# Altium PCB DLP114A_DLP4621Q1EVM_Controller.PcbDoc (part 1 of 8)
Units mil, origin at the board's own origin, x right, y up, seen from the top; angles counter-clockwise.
Board outline 4803.15 x 2598.43 mil, 14 copper layers (Top Layer, GND 1, SIGNAL 1, GND 2, SIGNAL 2, PWR SPLIT PLANE 1, GND 3, GND 4, PWR SPLIT PLANE 2, SIGNAL 3, GND 5, SIGNAL 4, GND 6, Bottom Layer), stack 91.4 mil thick; 489 components, 394 nets, 1925 pads, 1273 vias.
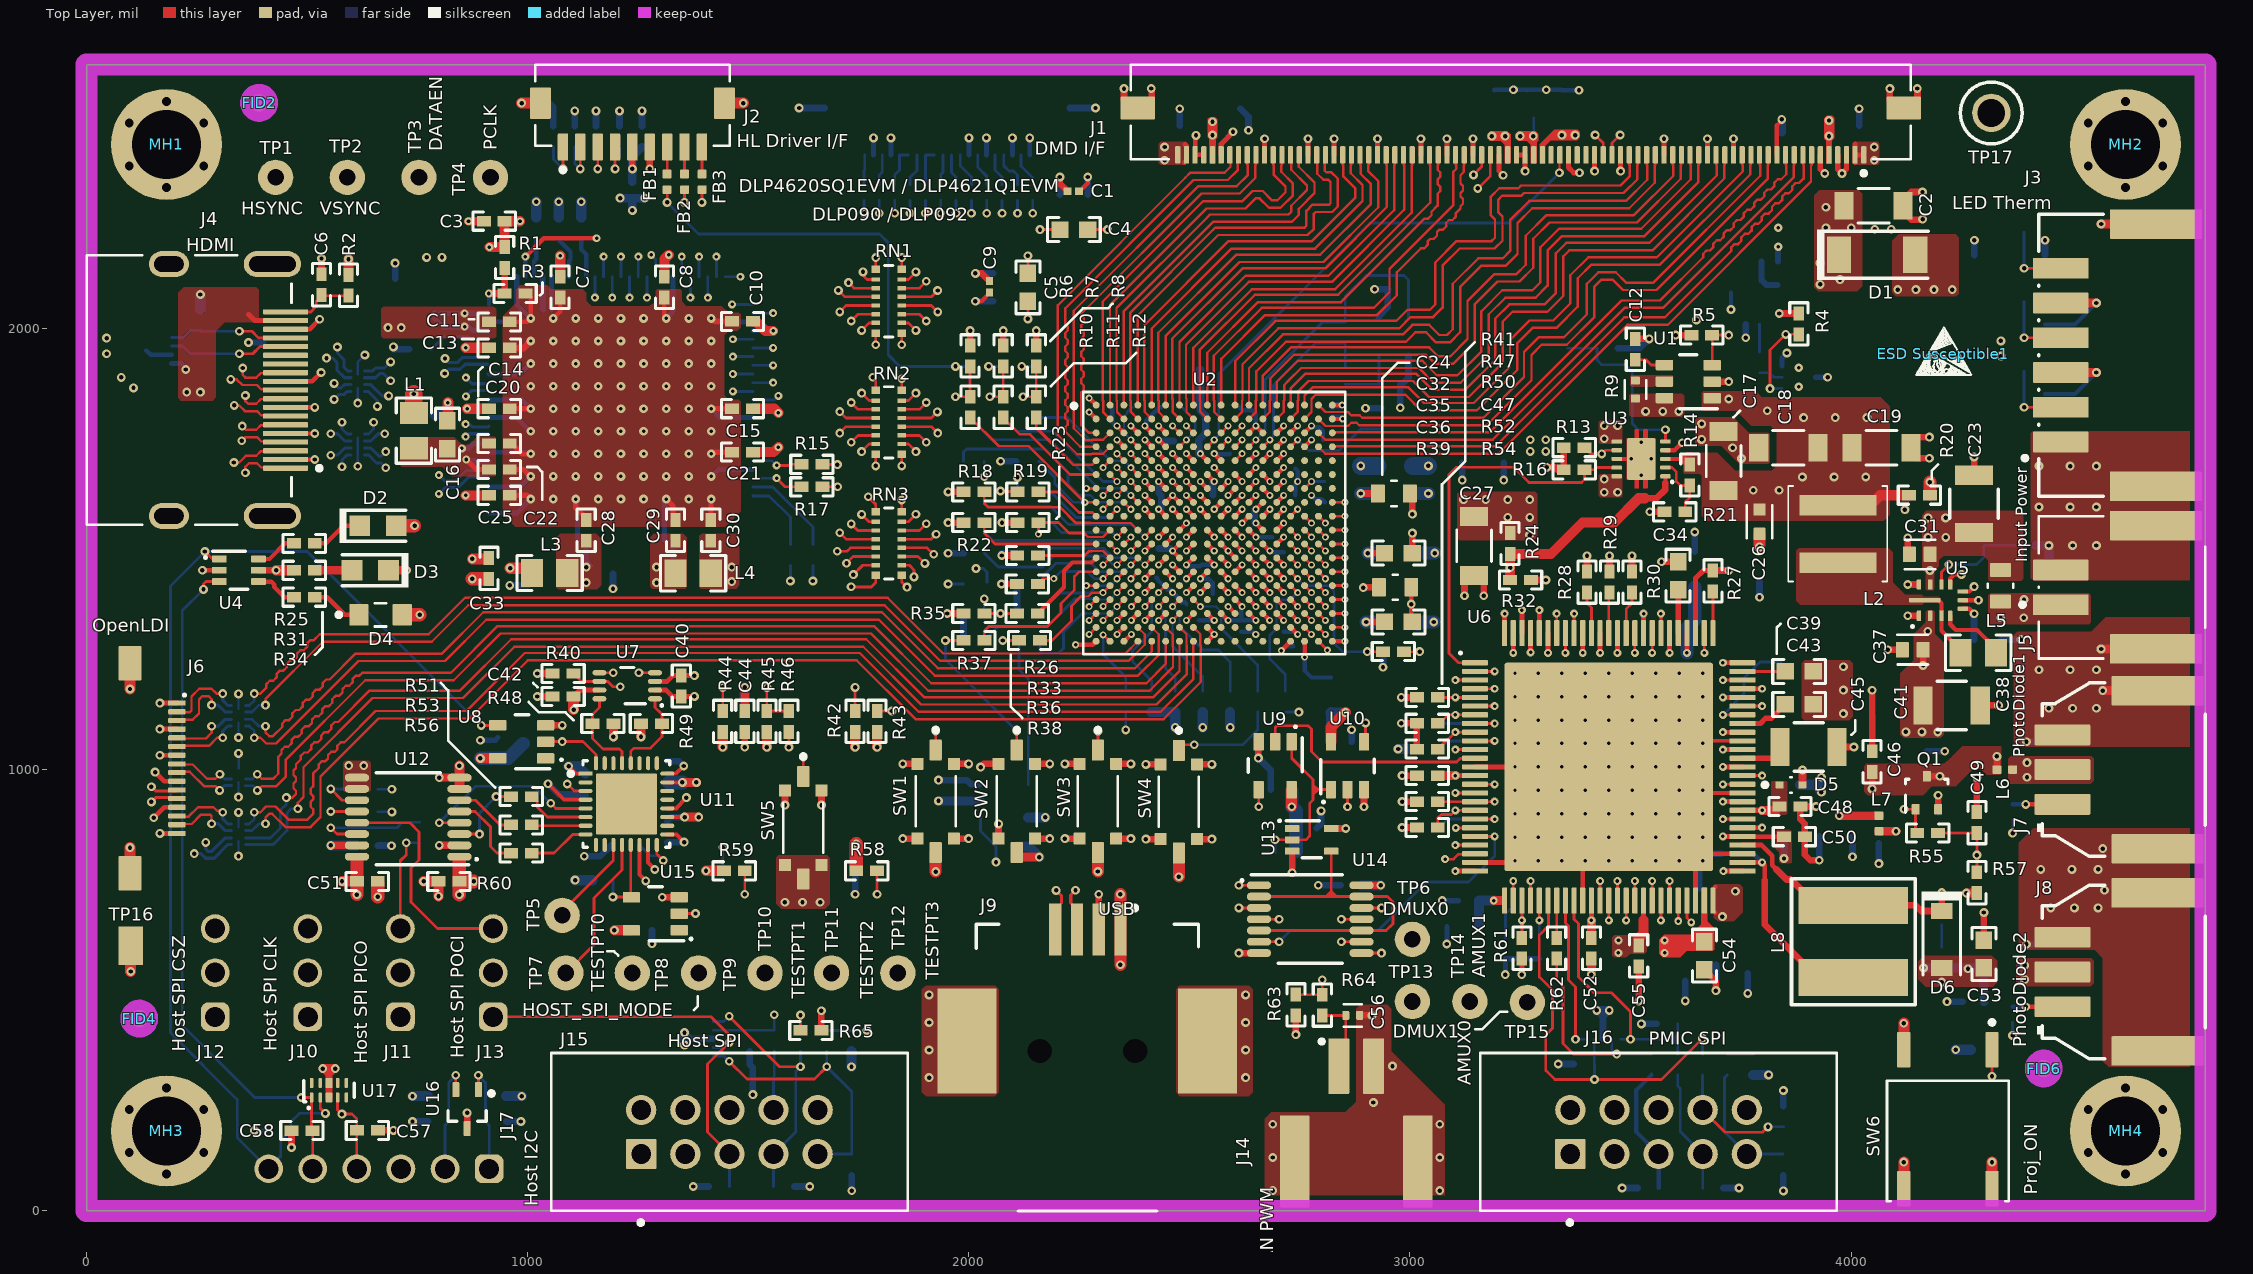
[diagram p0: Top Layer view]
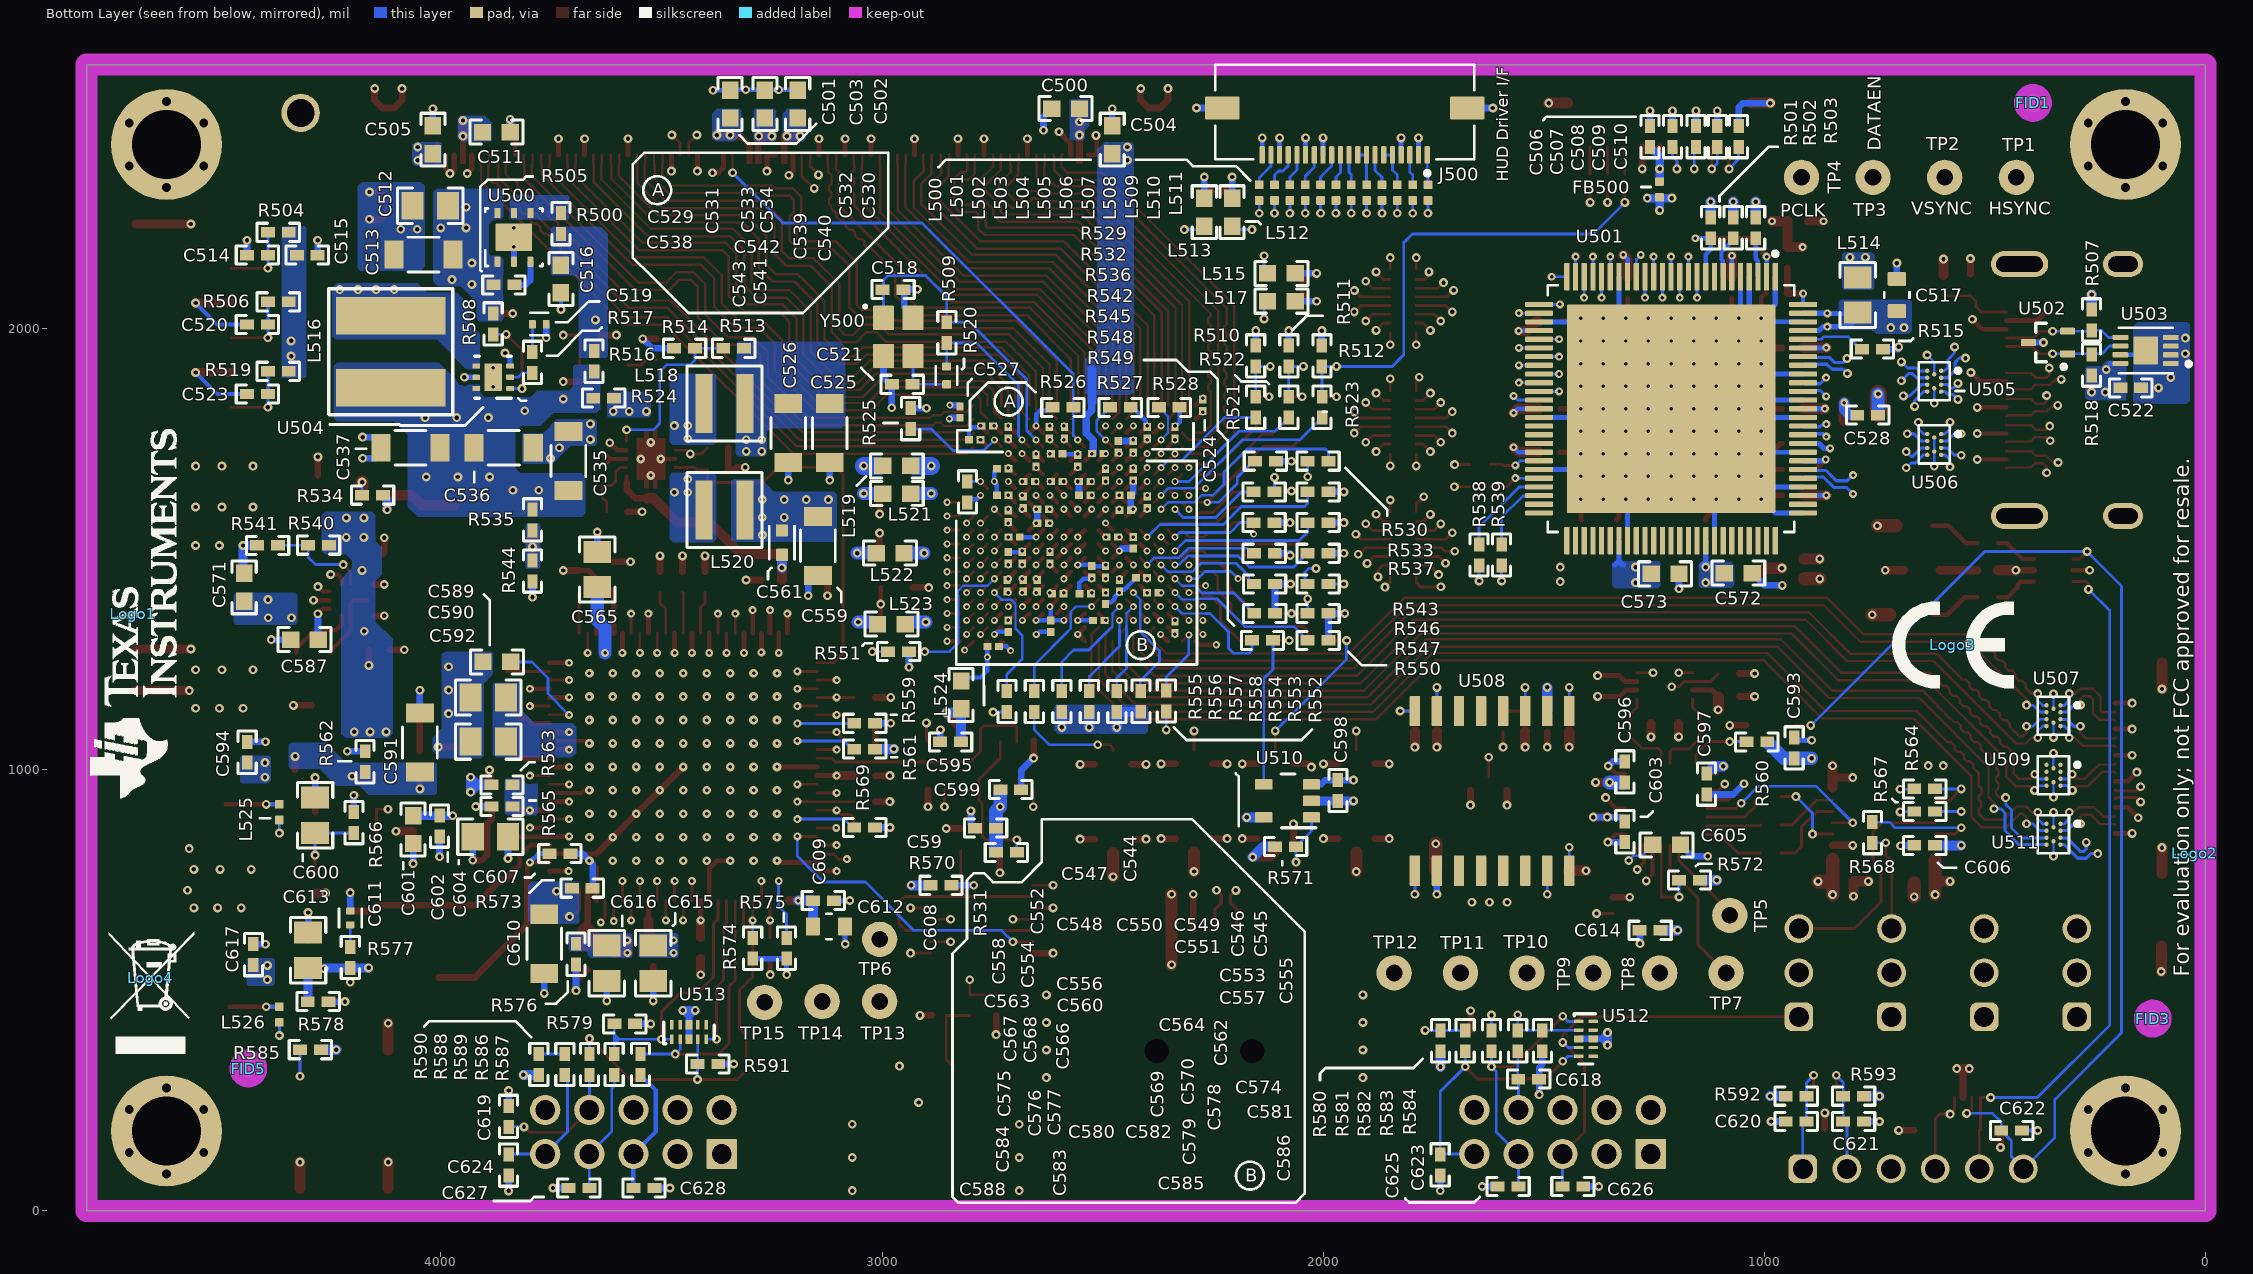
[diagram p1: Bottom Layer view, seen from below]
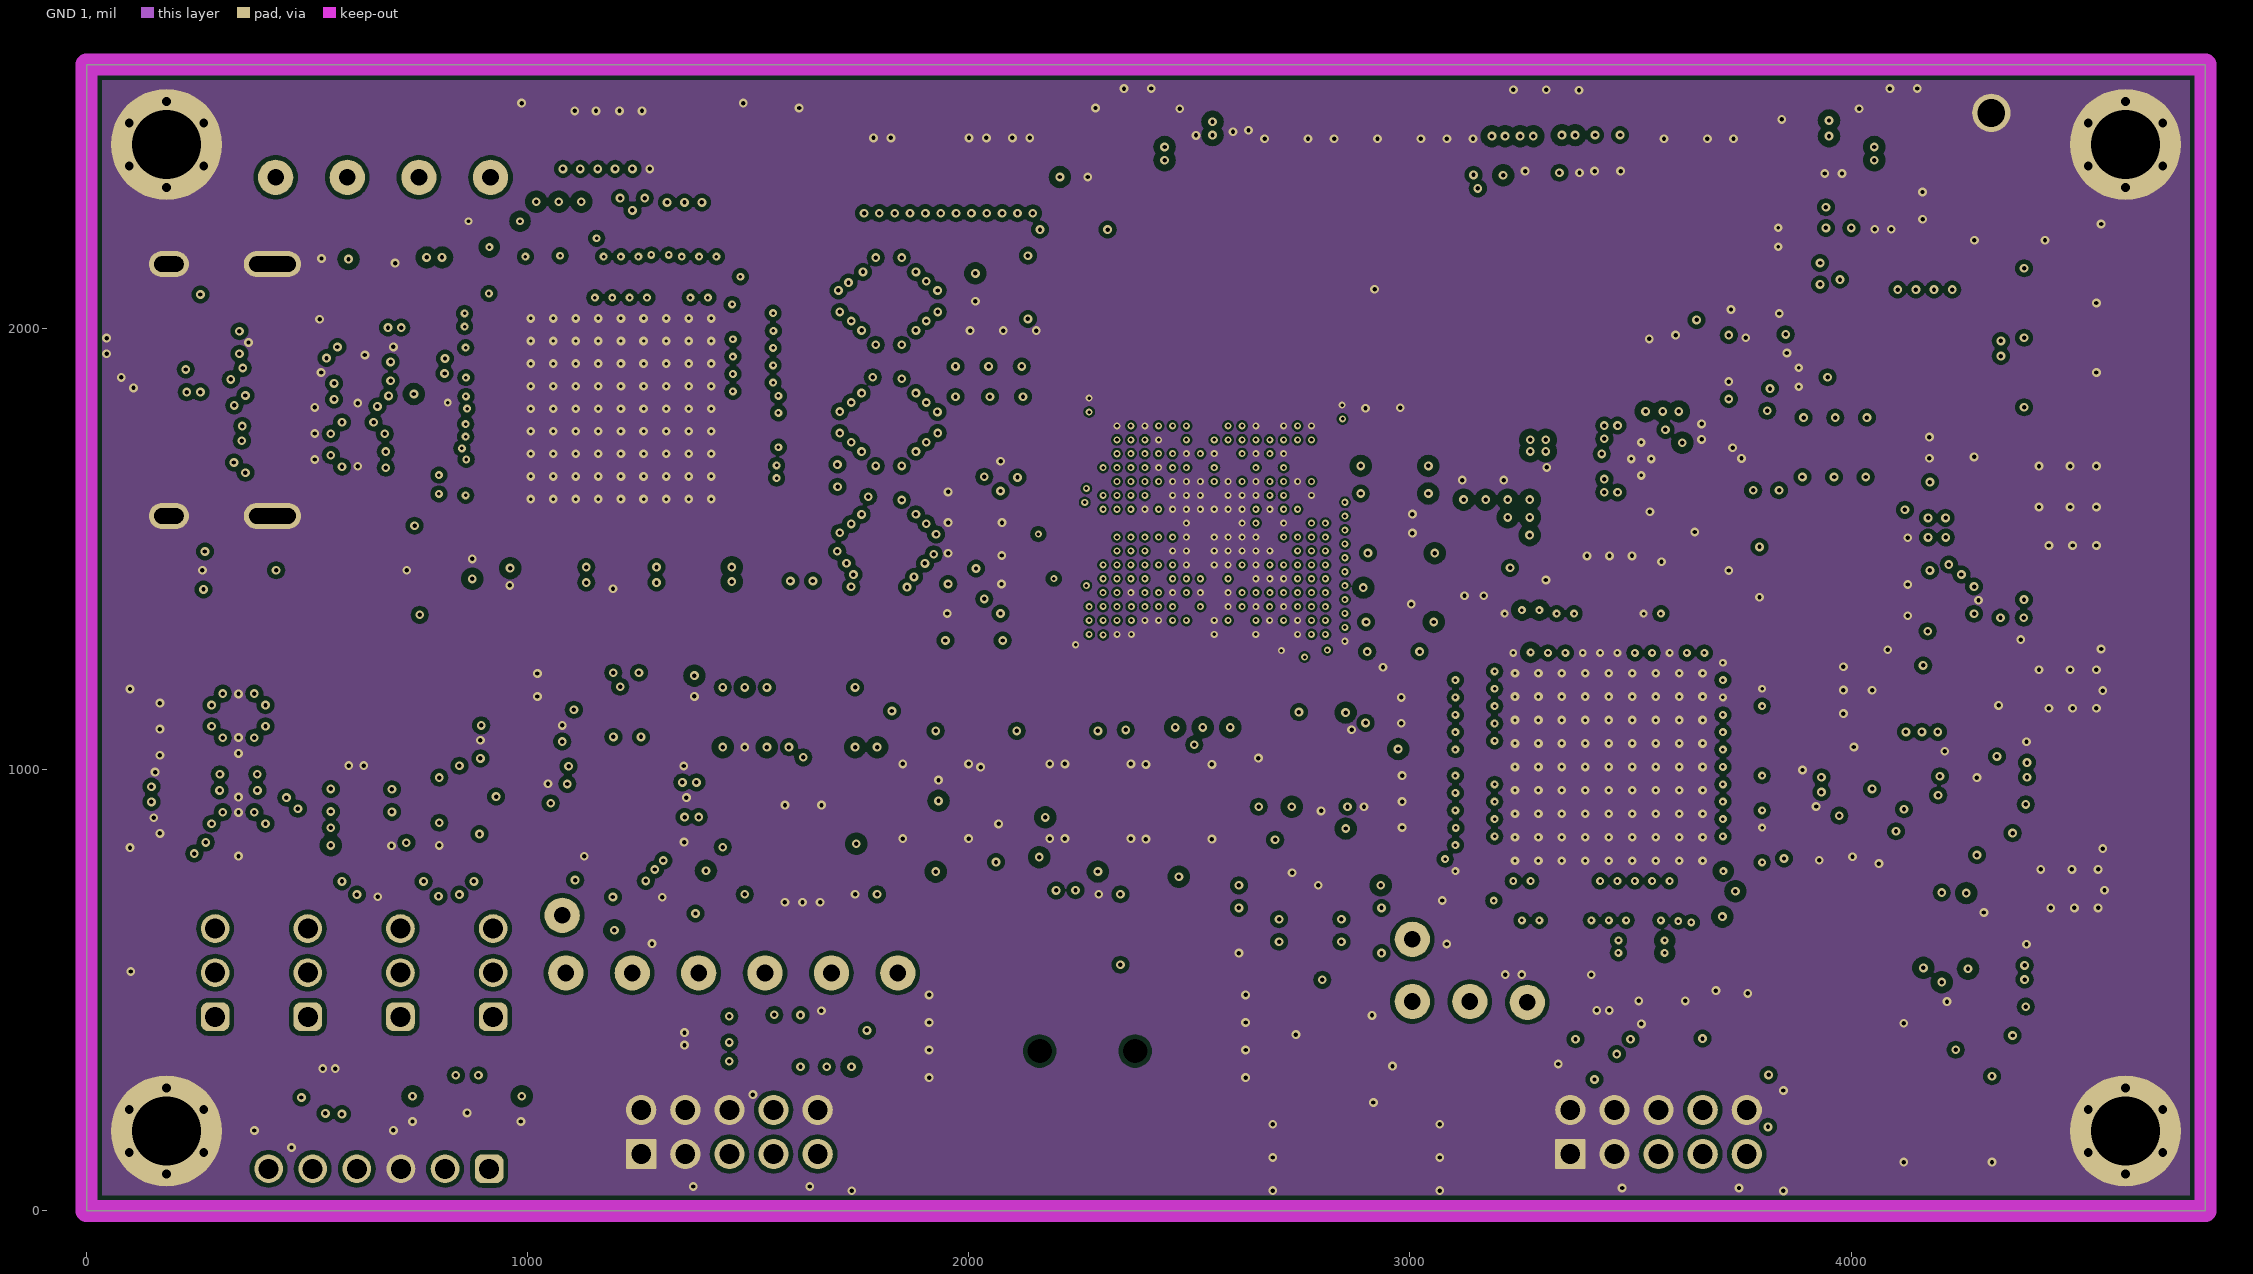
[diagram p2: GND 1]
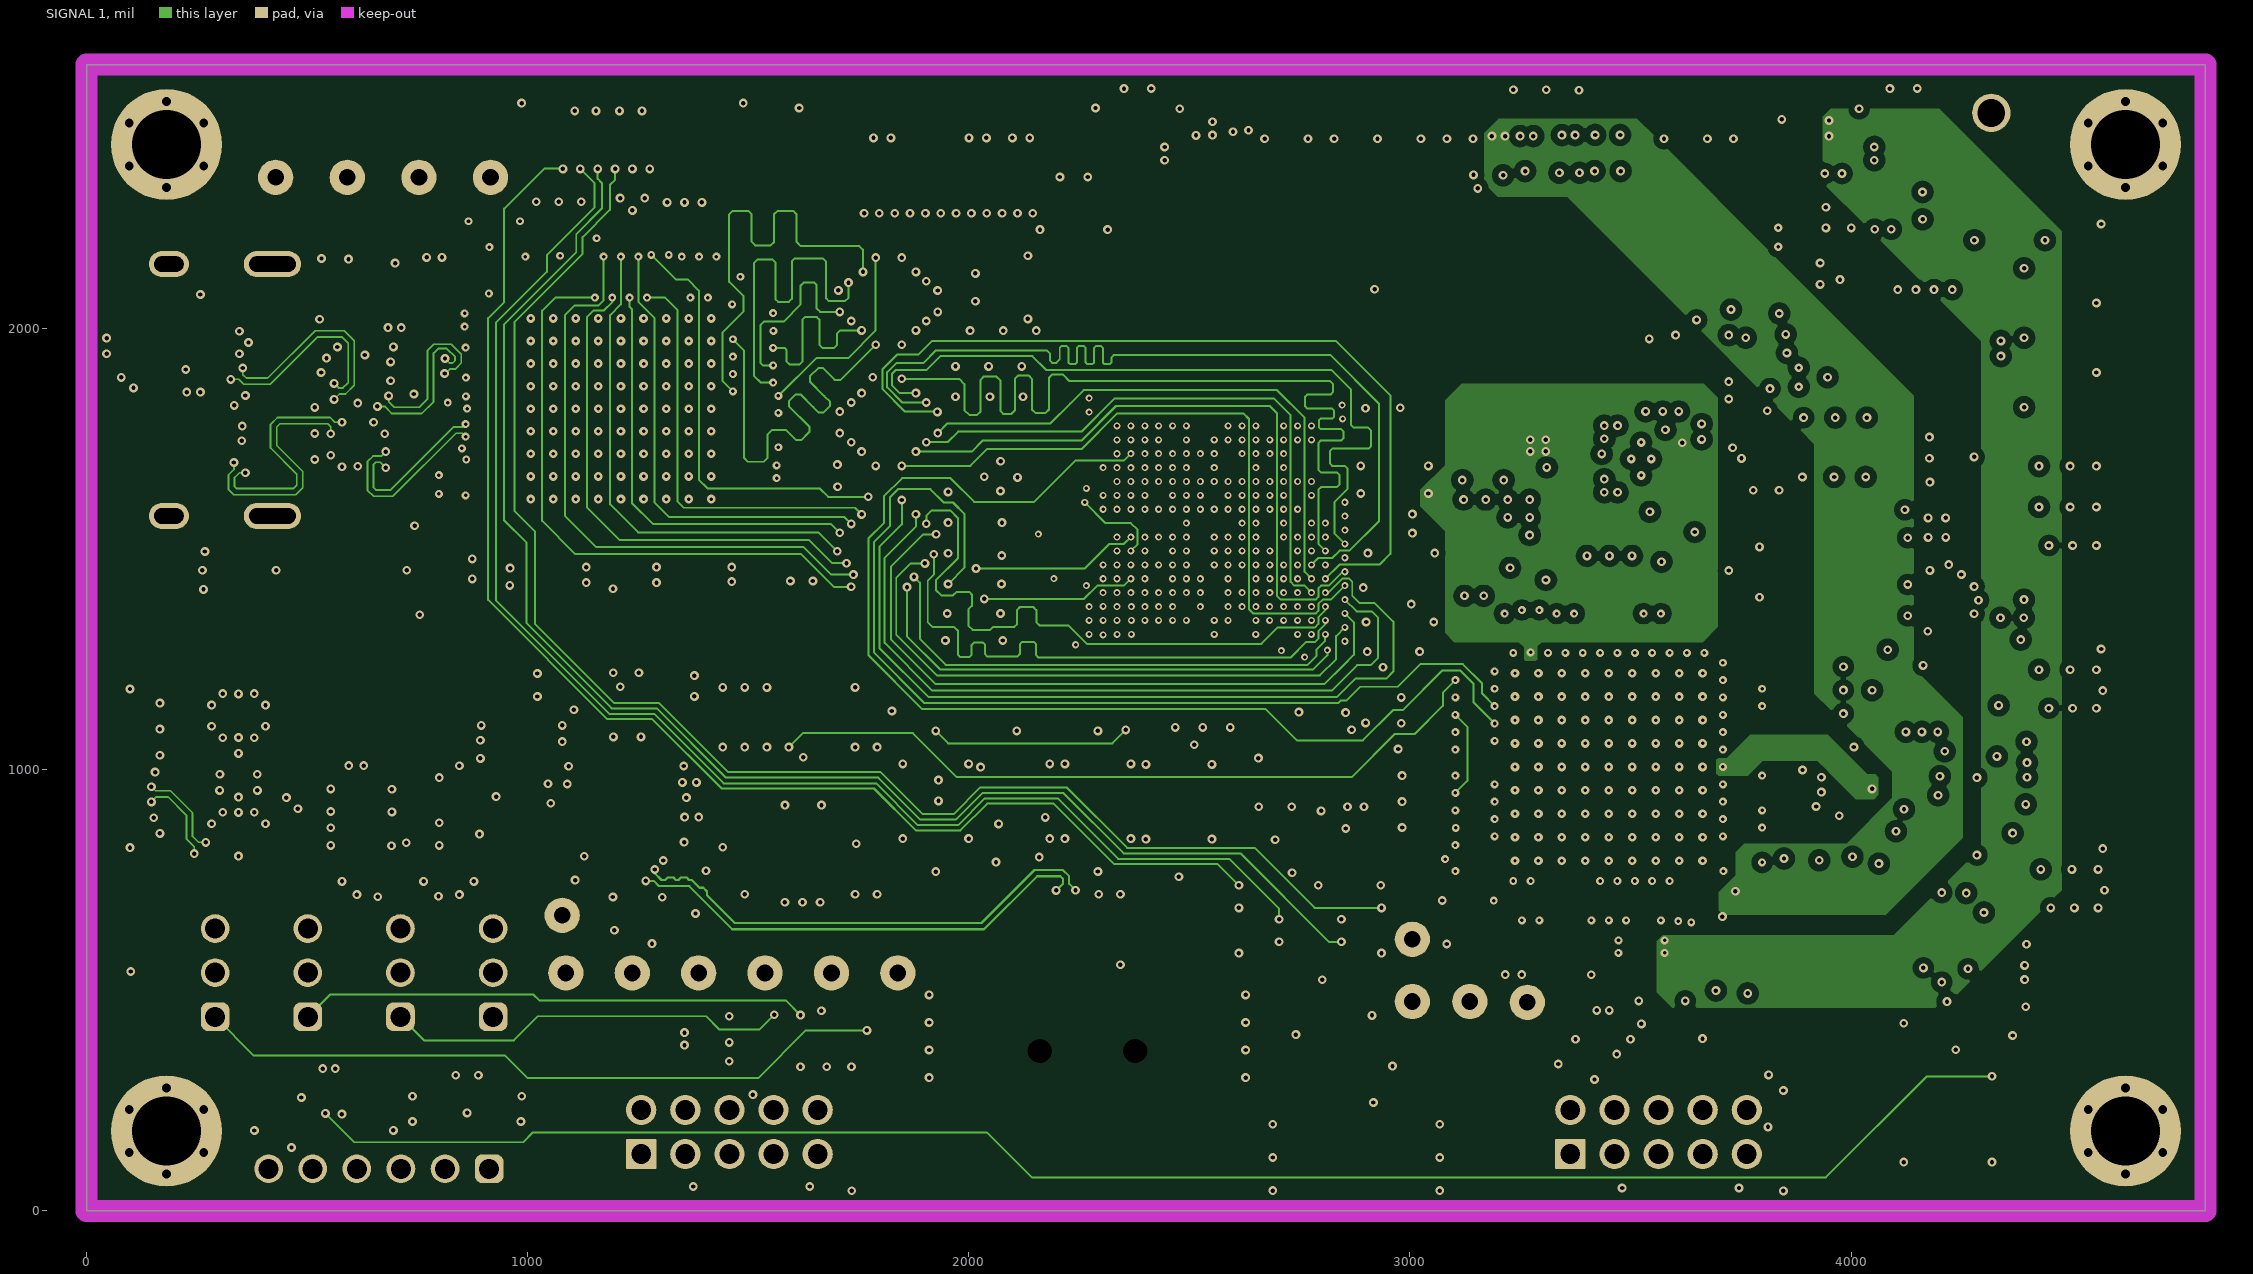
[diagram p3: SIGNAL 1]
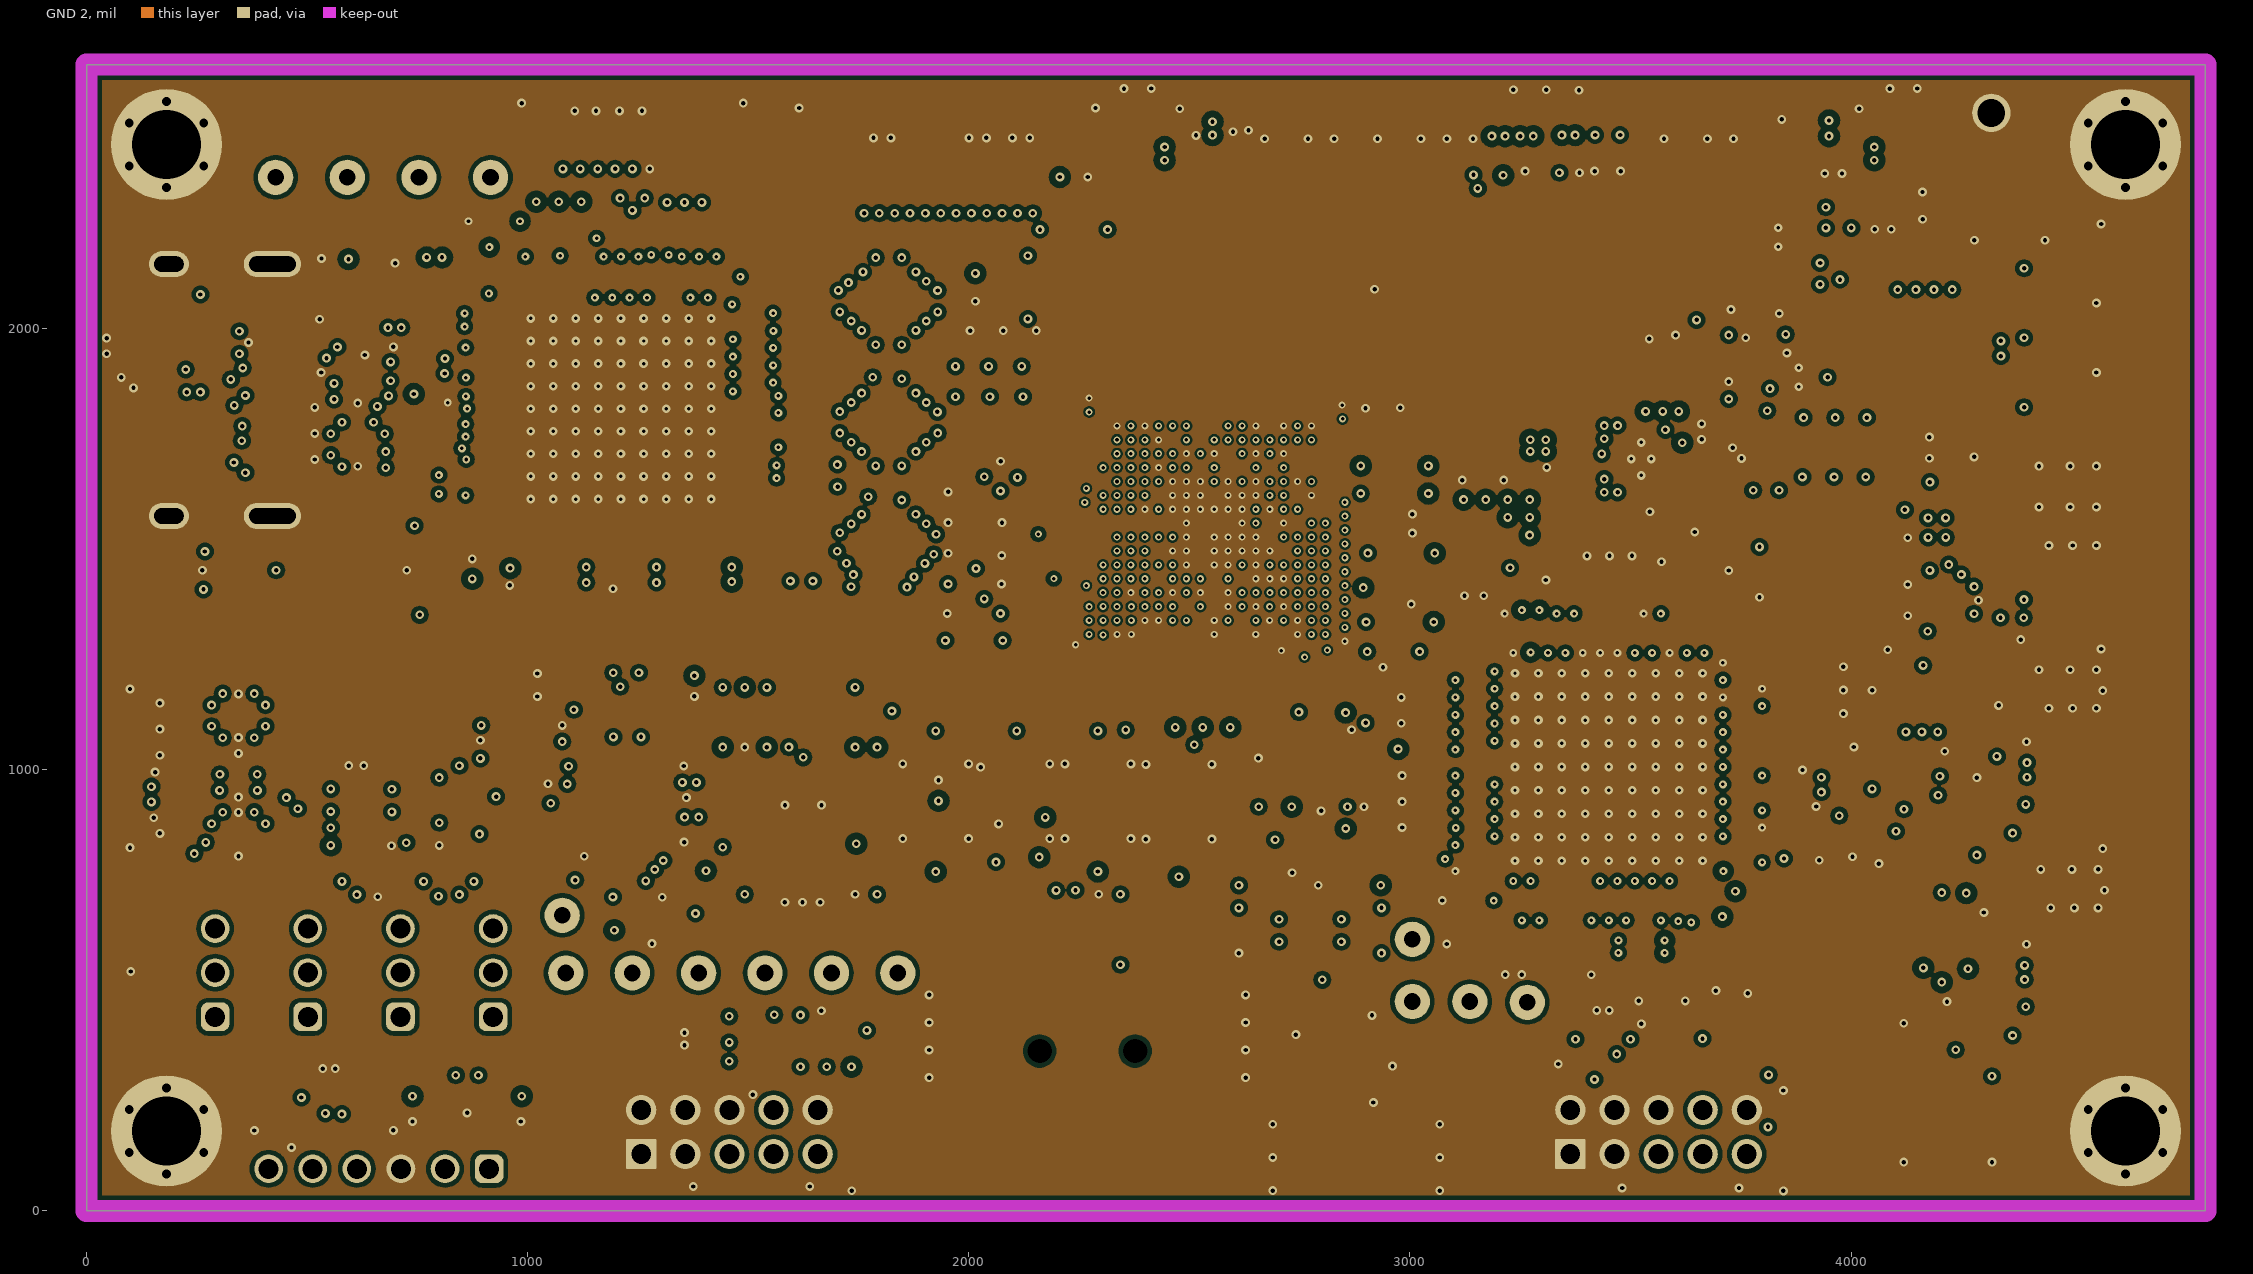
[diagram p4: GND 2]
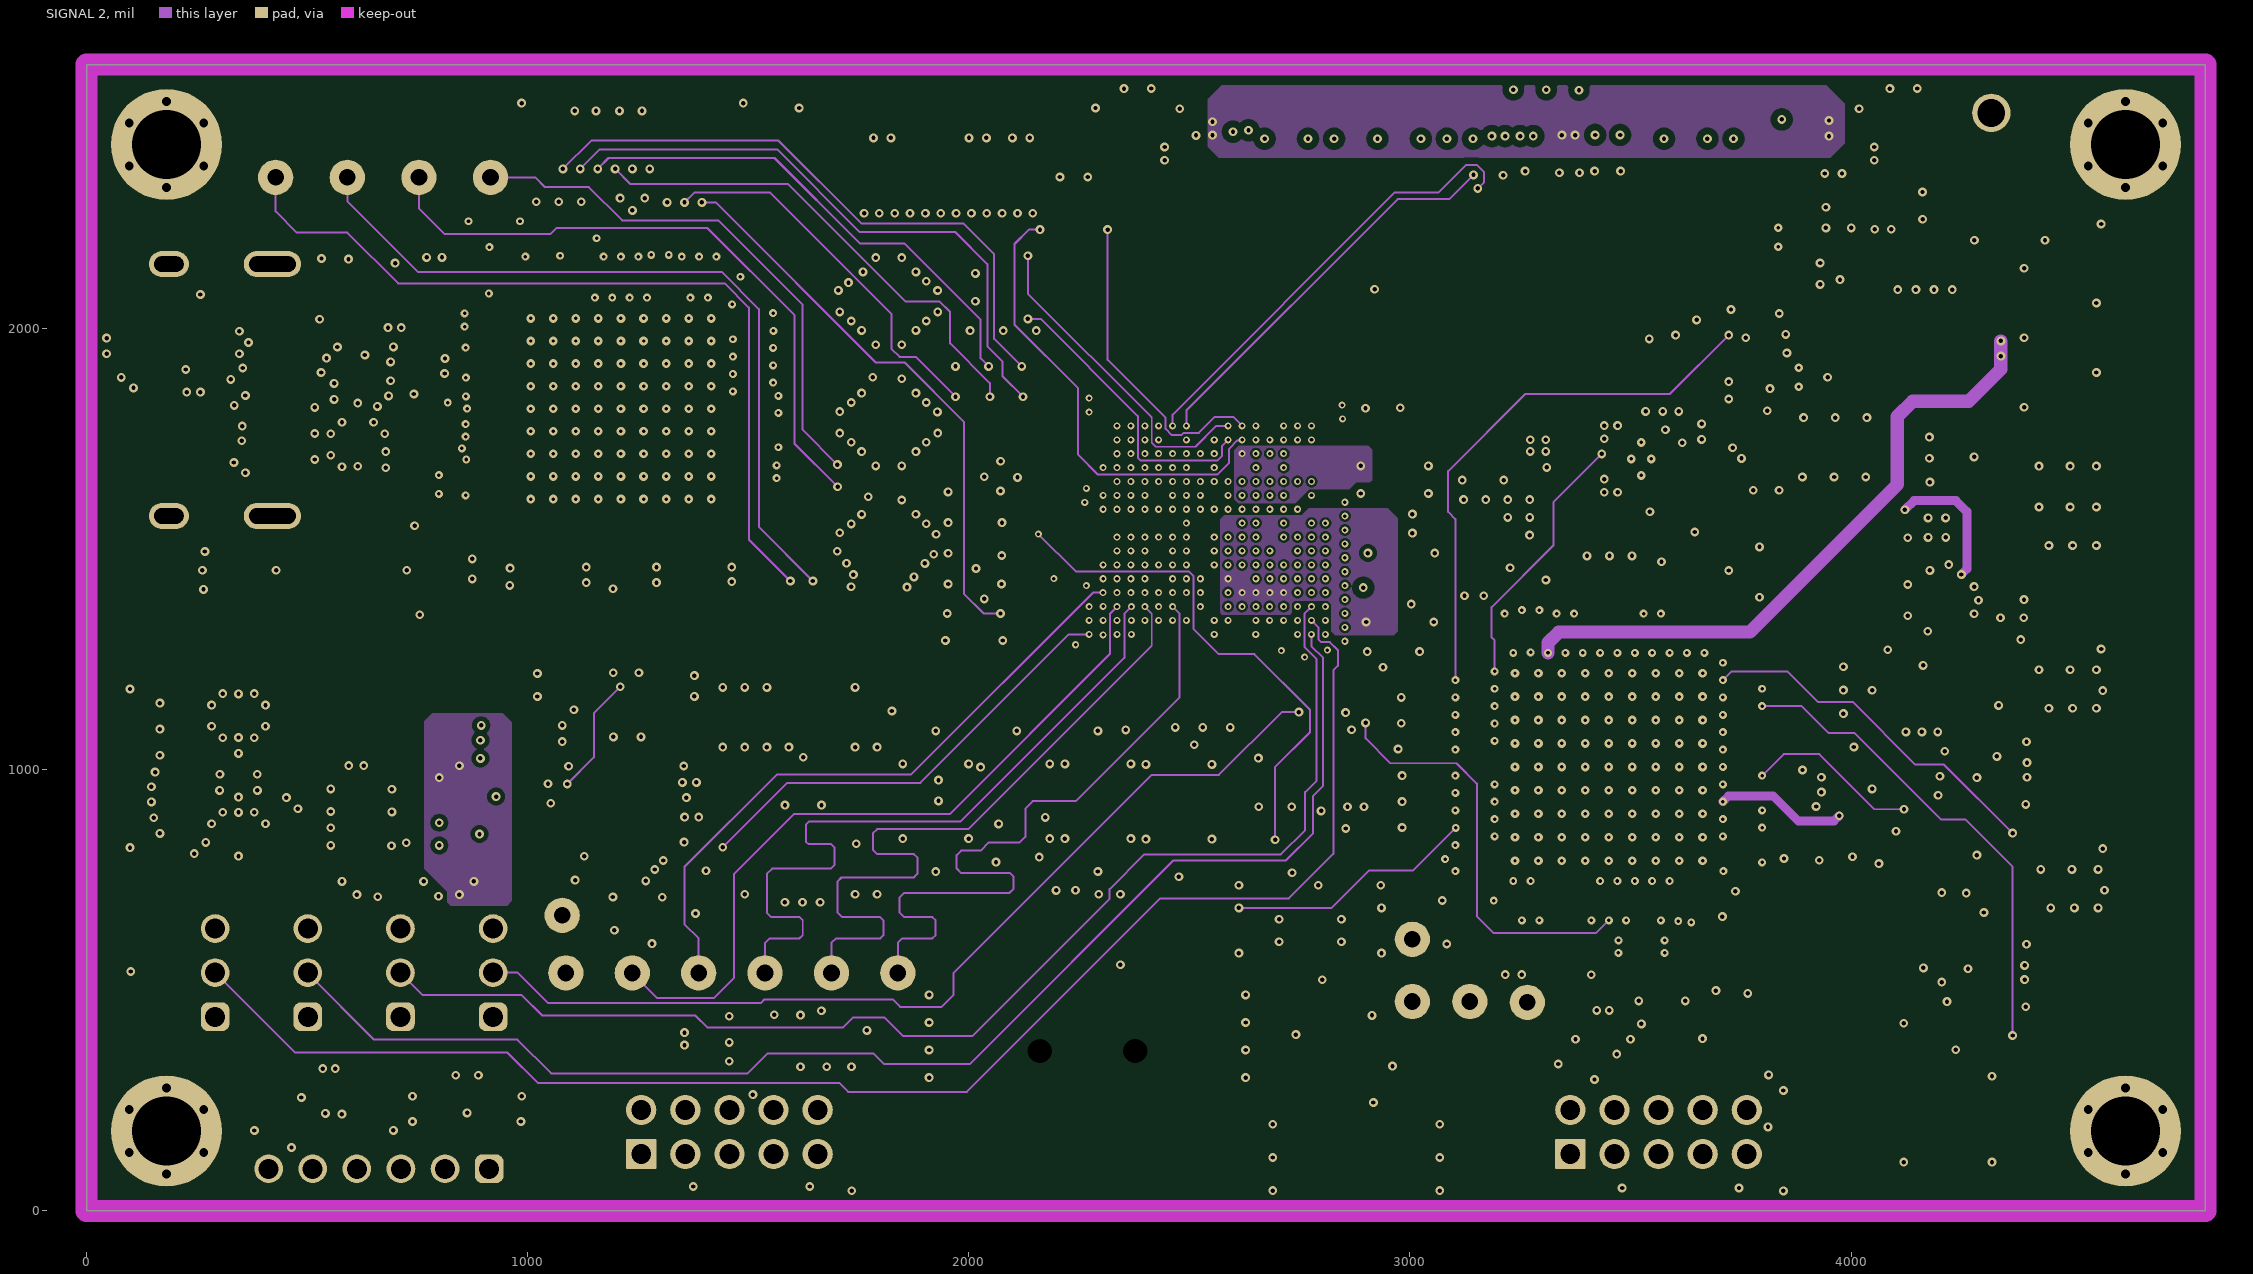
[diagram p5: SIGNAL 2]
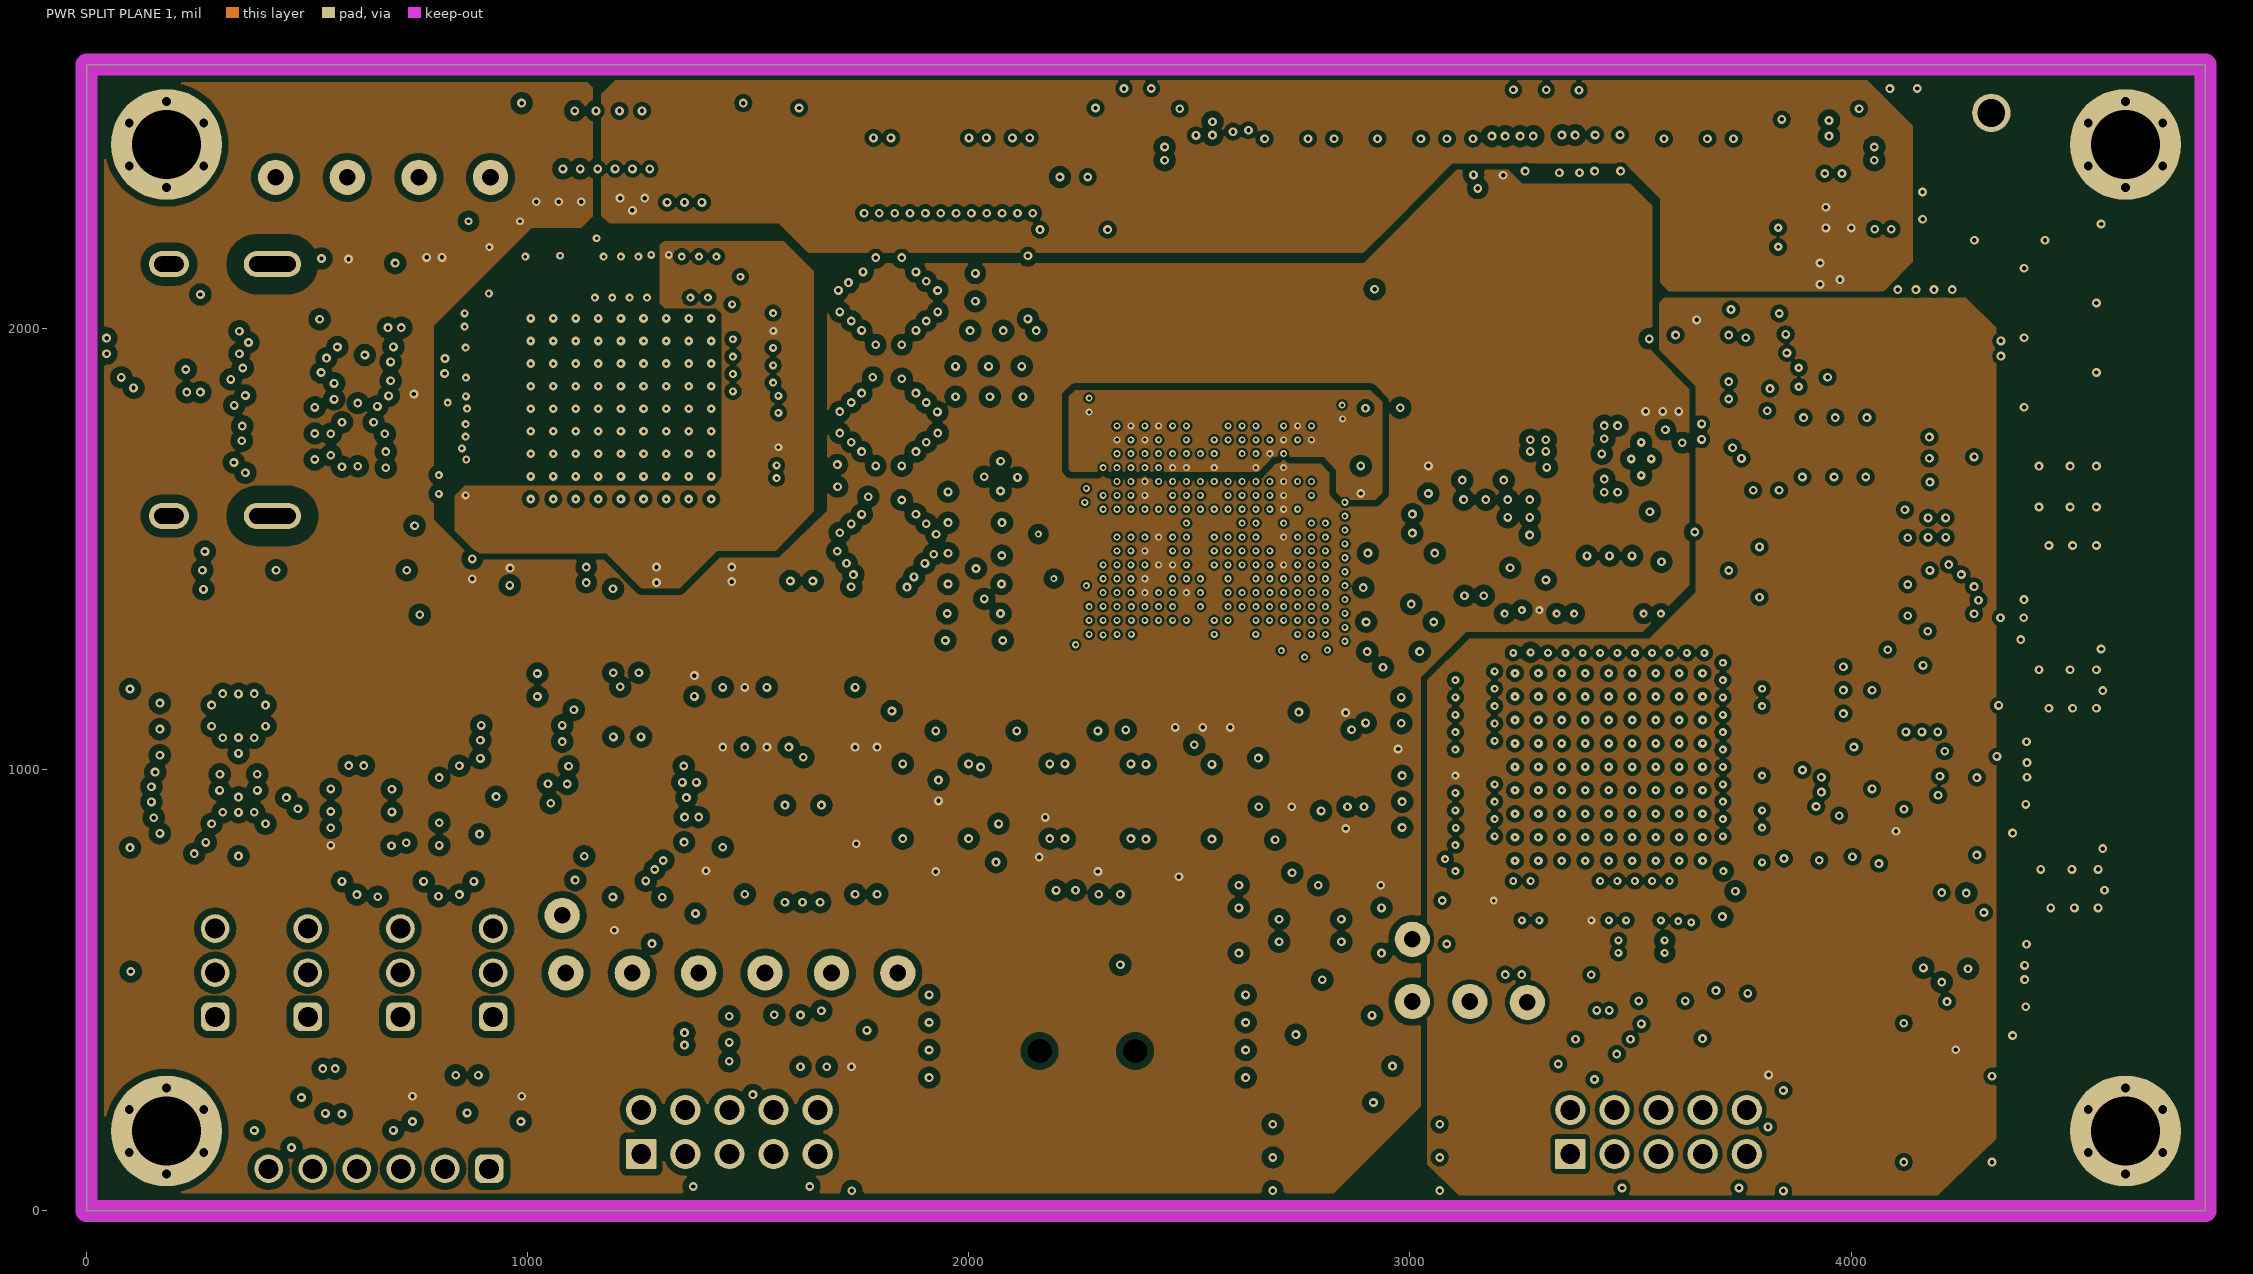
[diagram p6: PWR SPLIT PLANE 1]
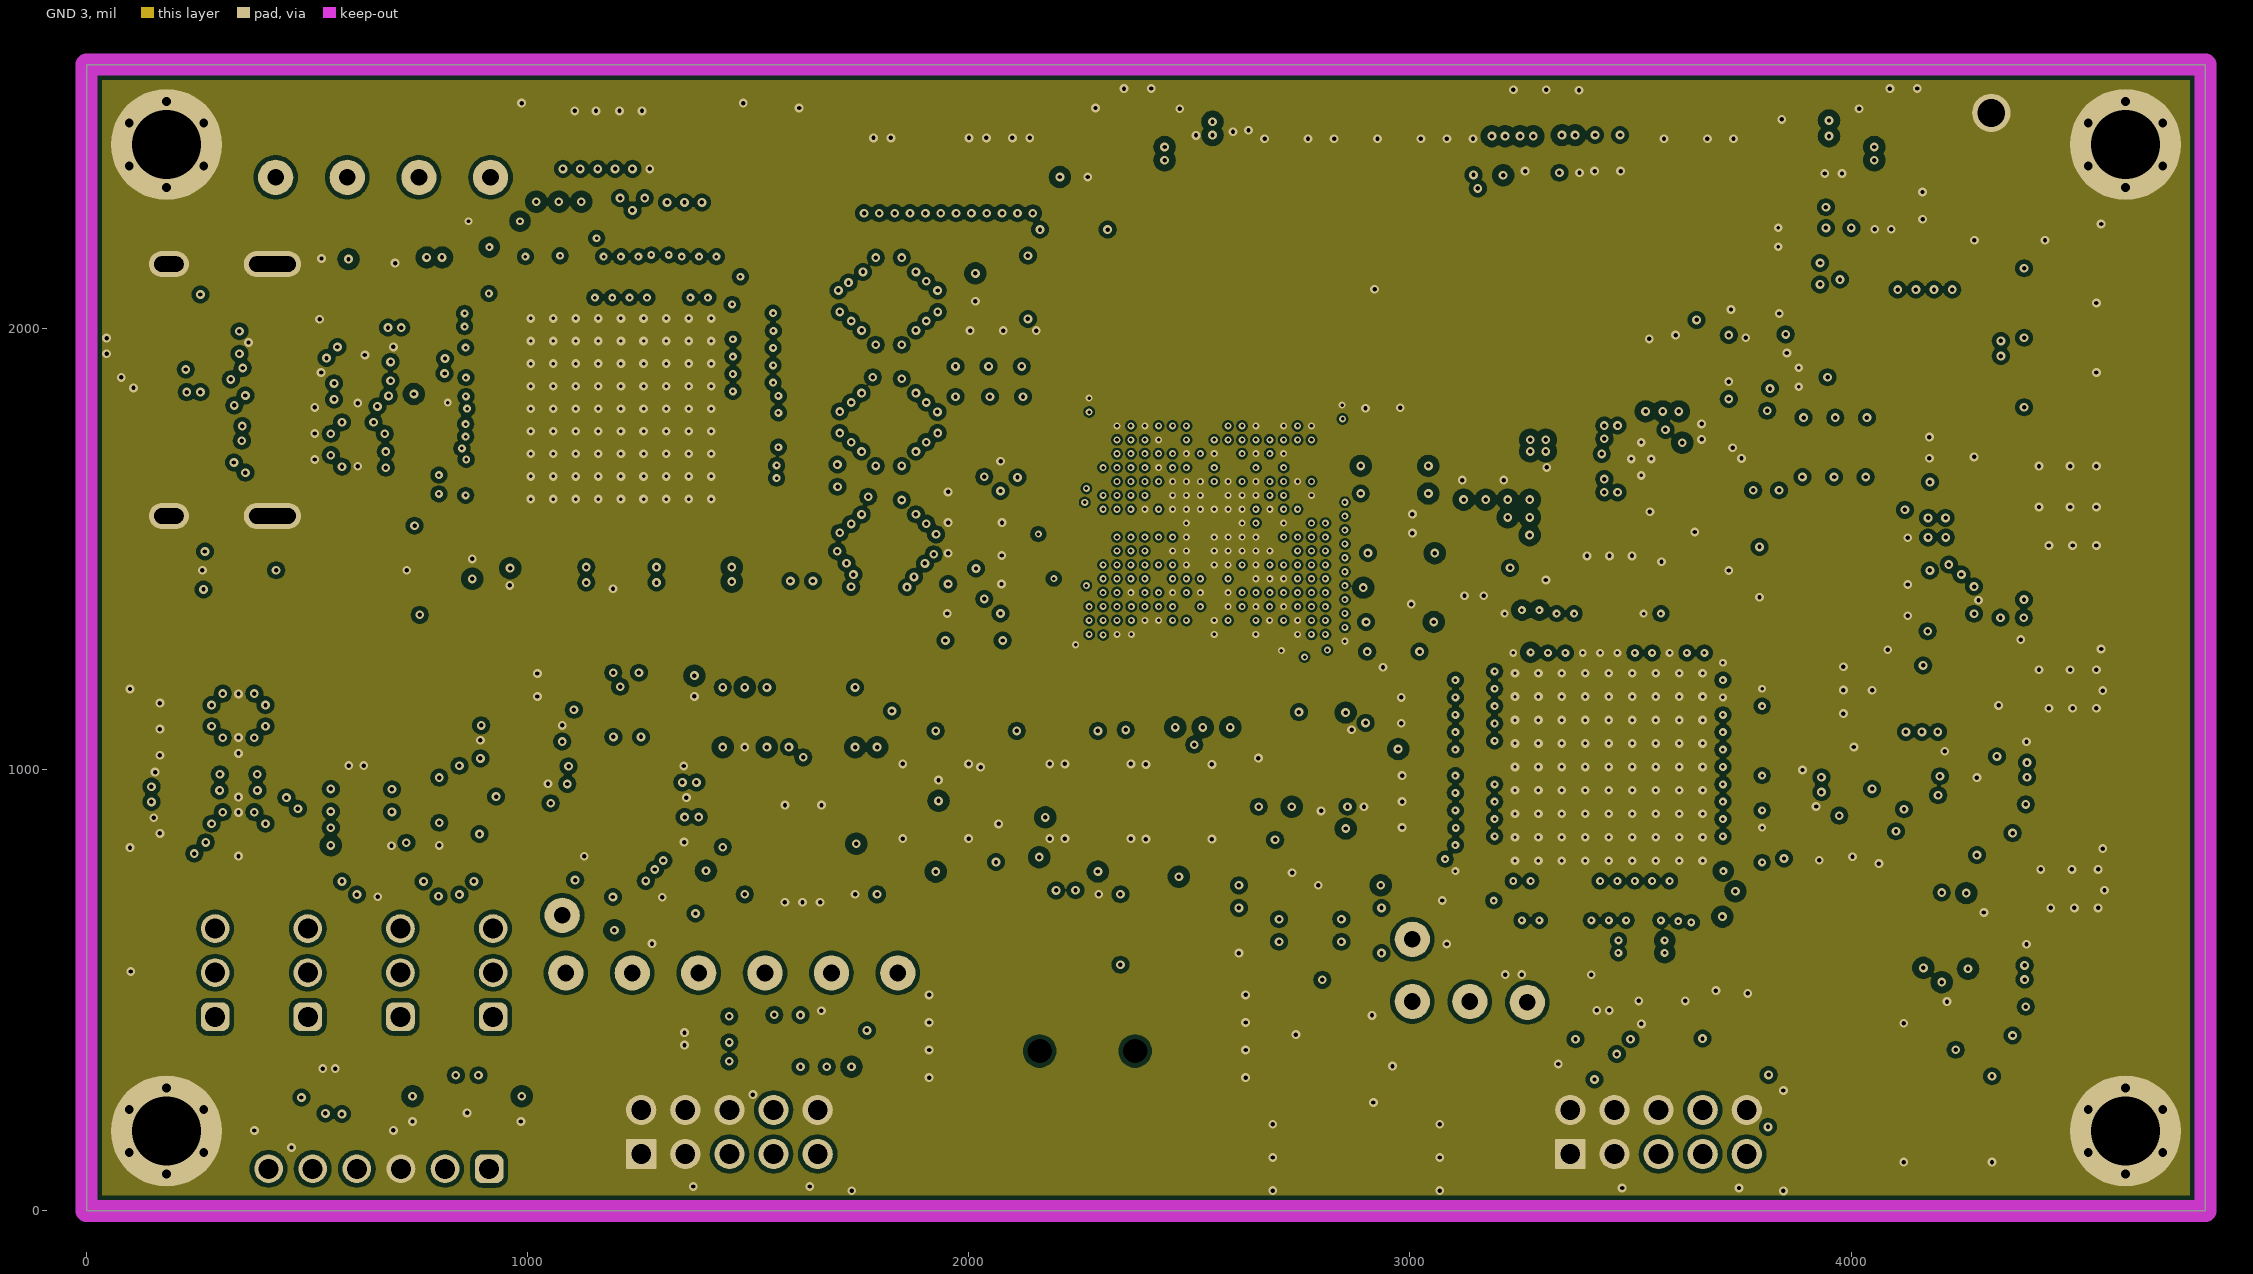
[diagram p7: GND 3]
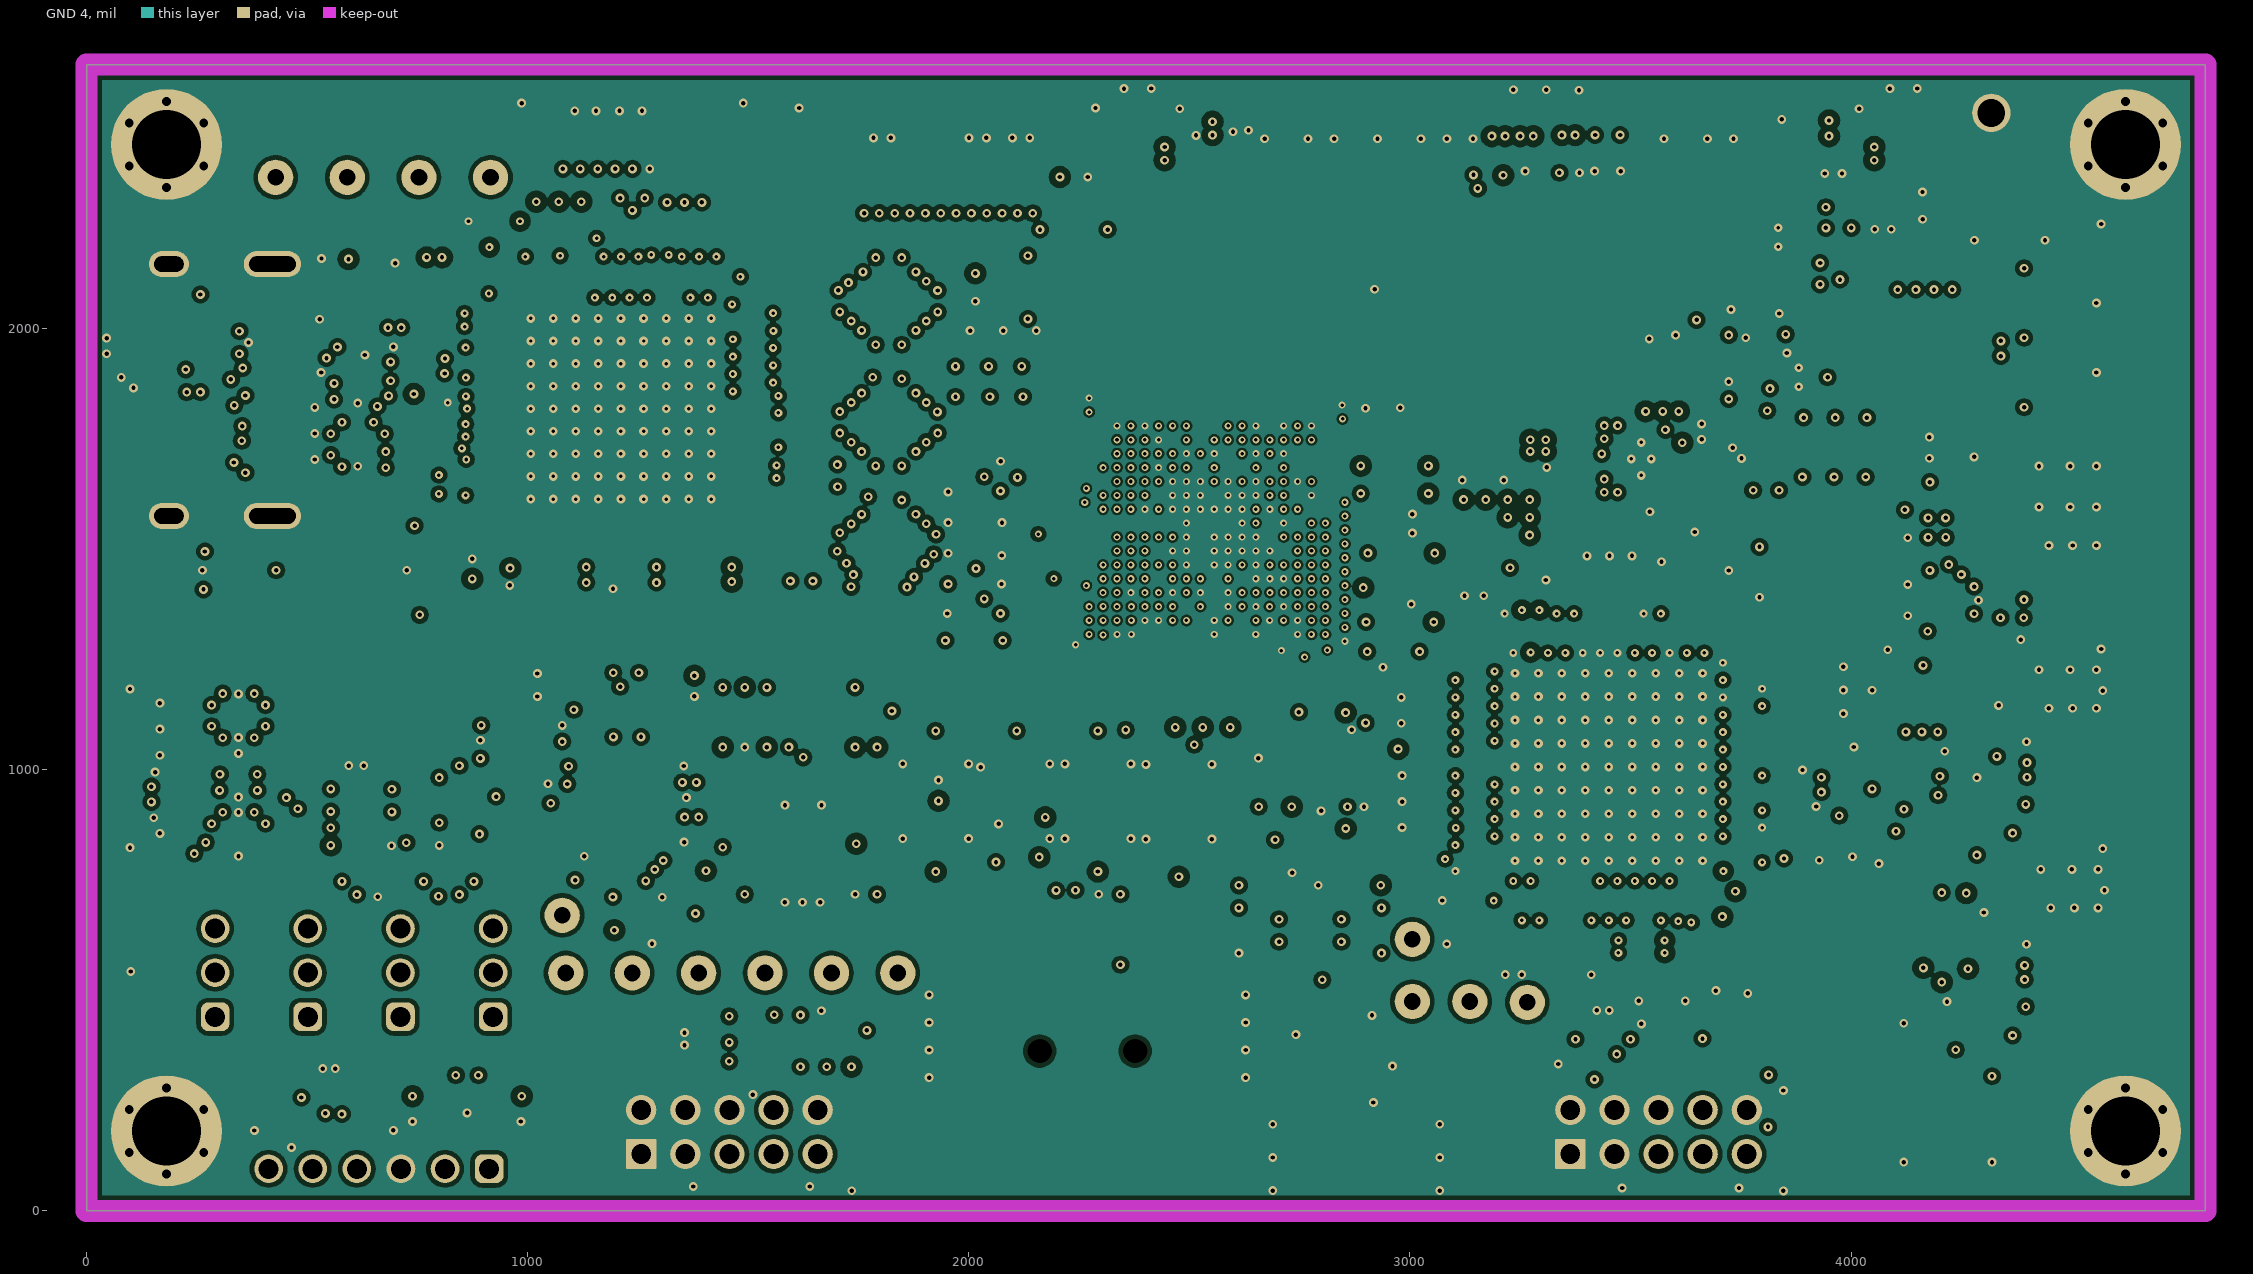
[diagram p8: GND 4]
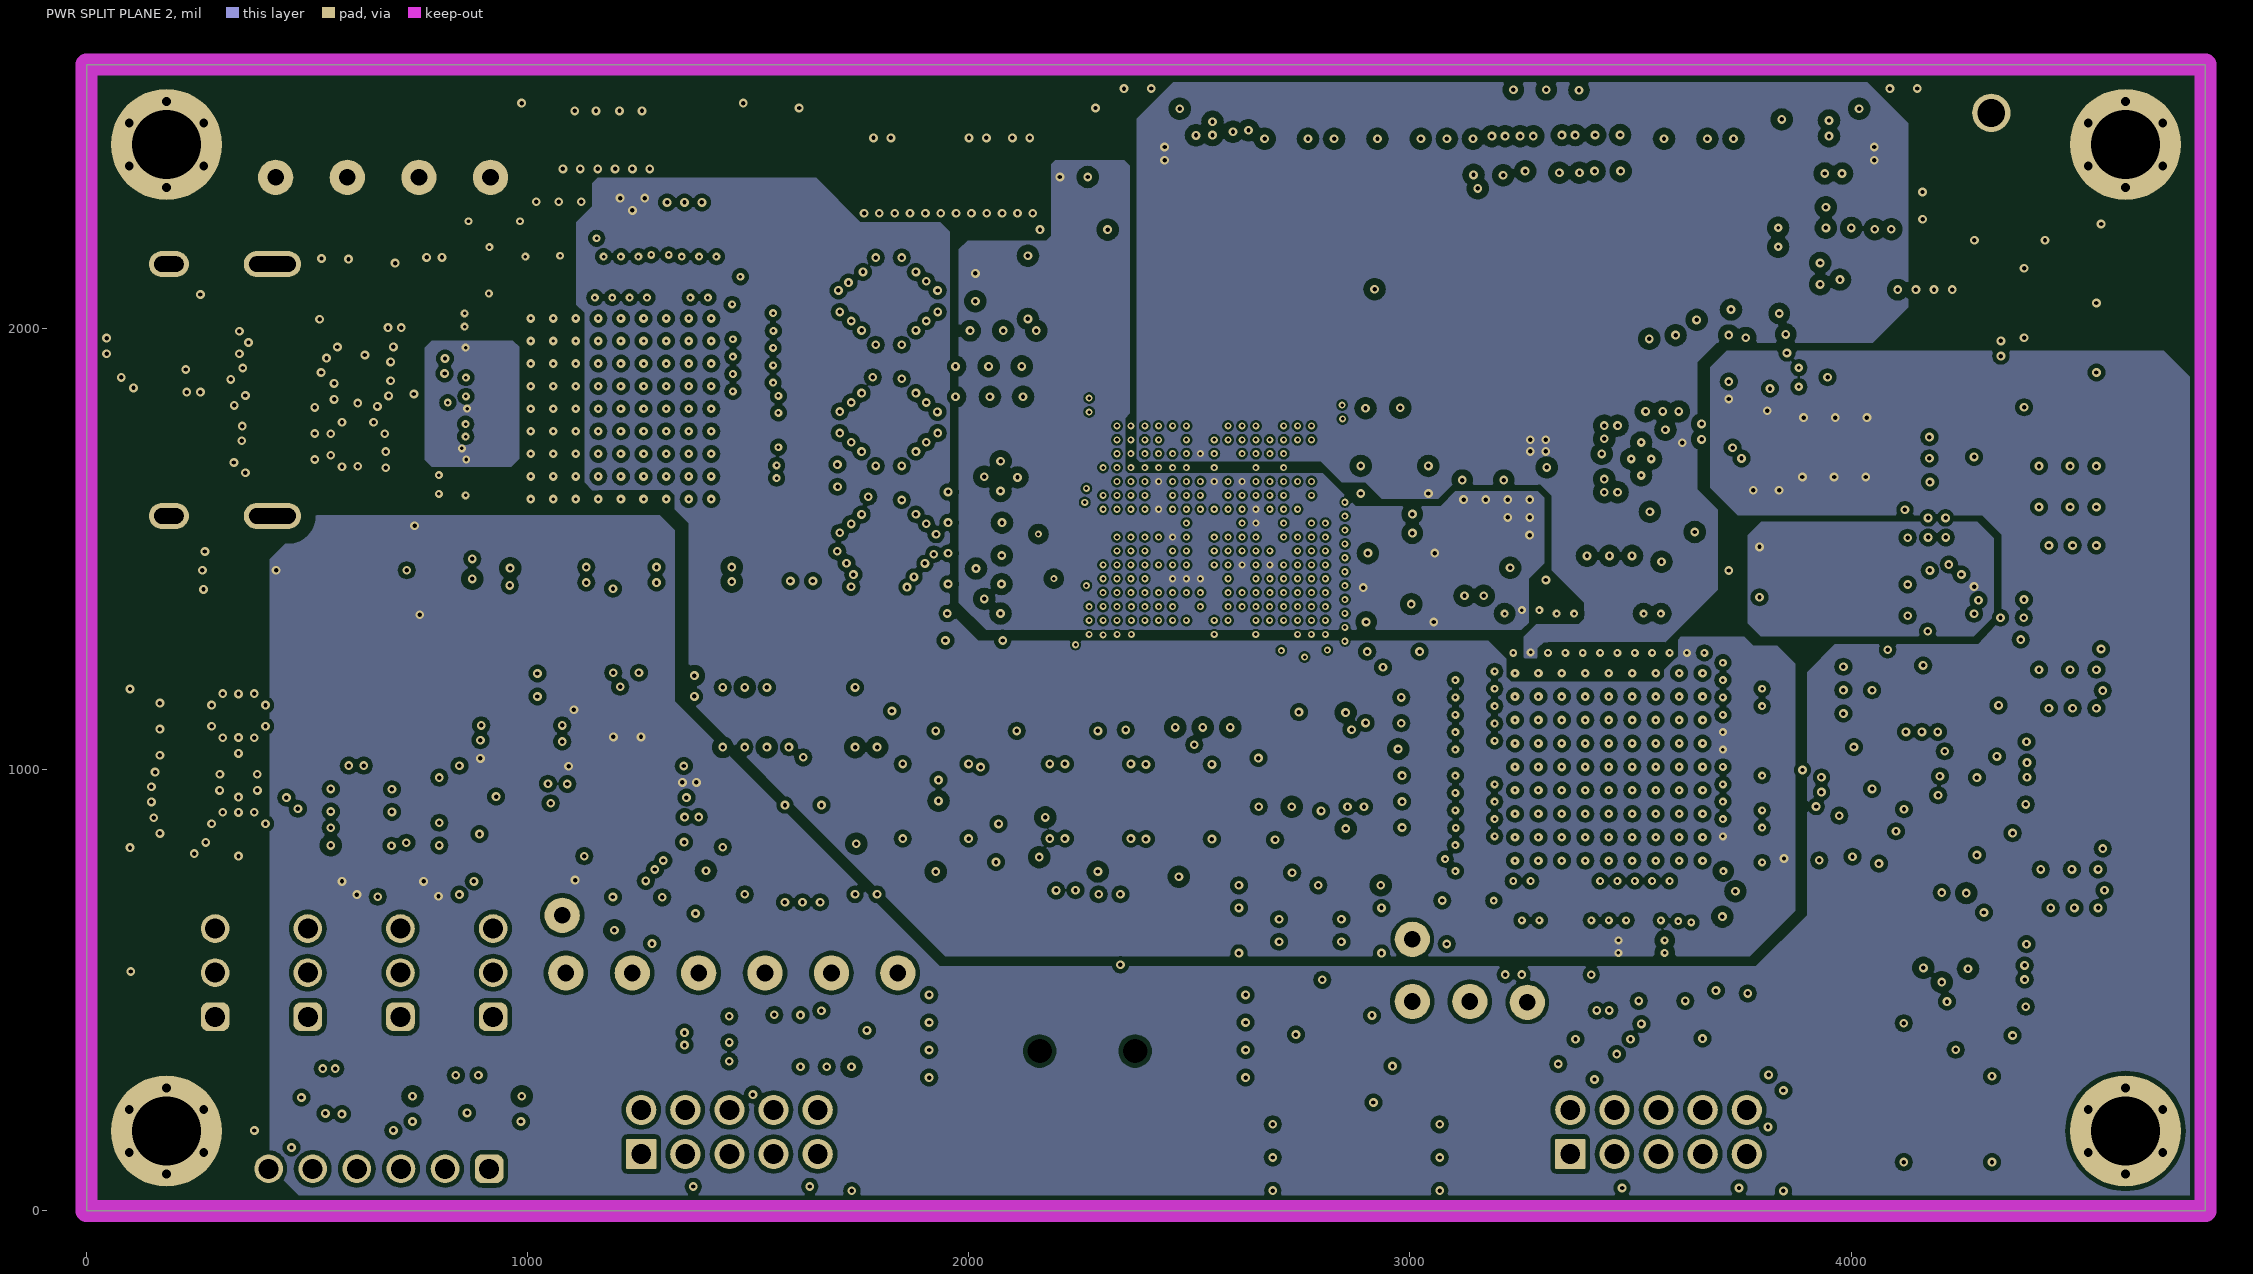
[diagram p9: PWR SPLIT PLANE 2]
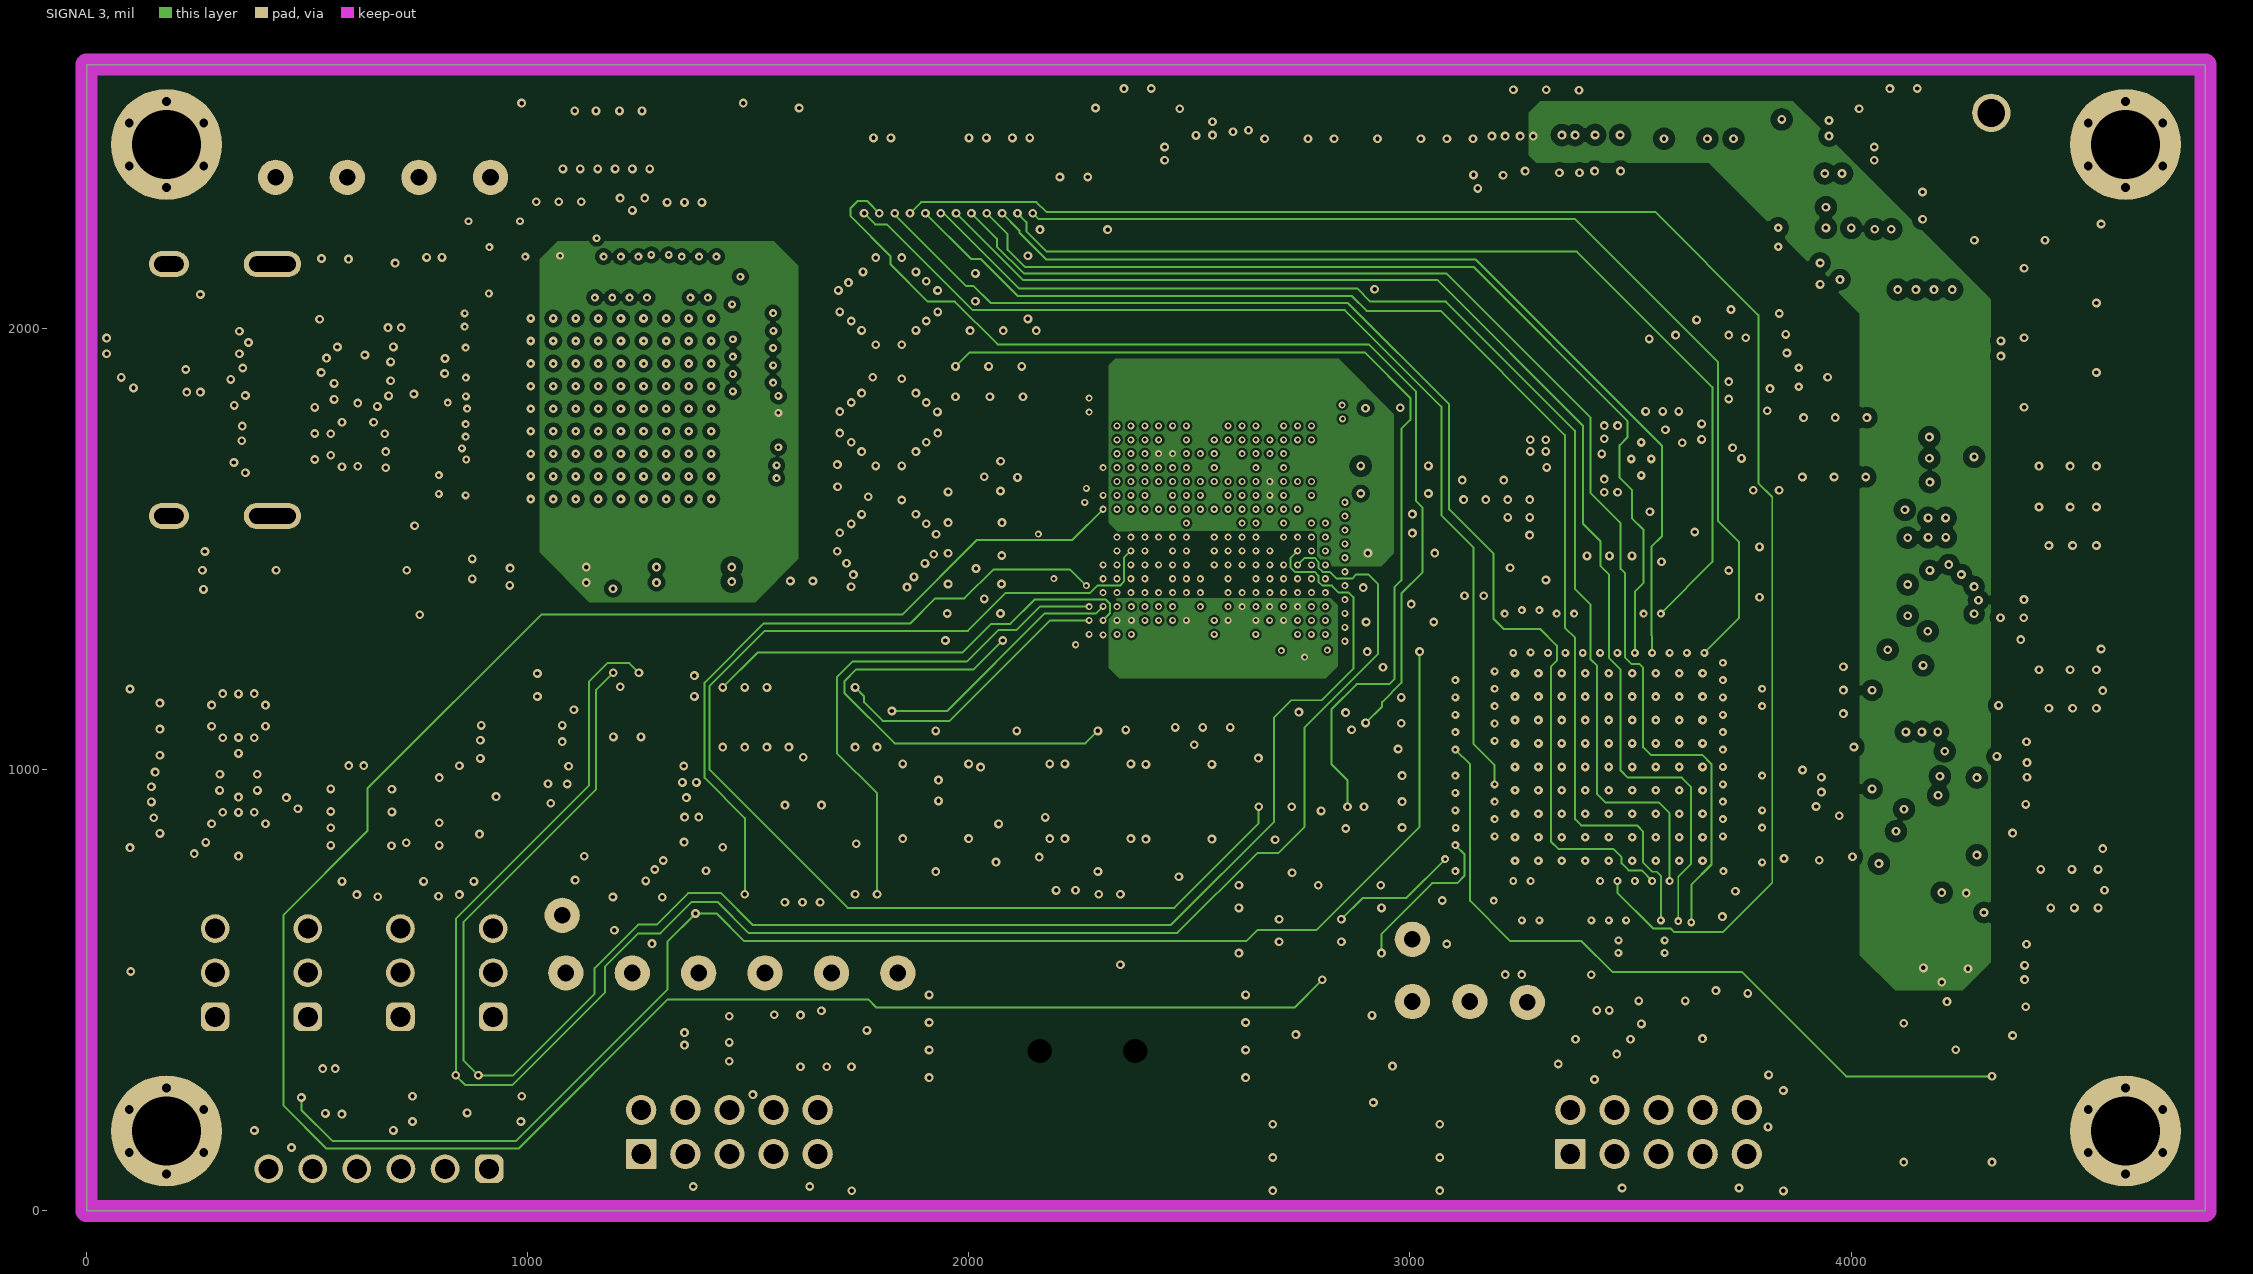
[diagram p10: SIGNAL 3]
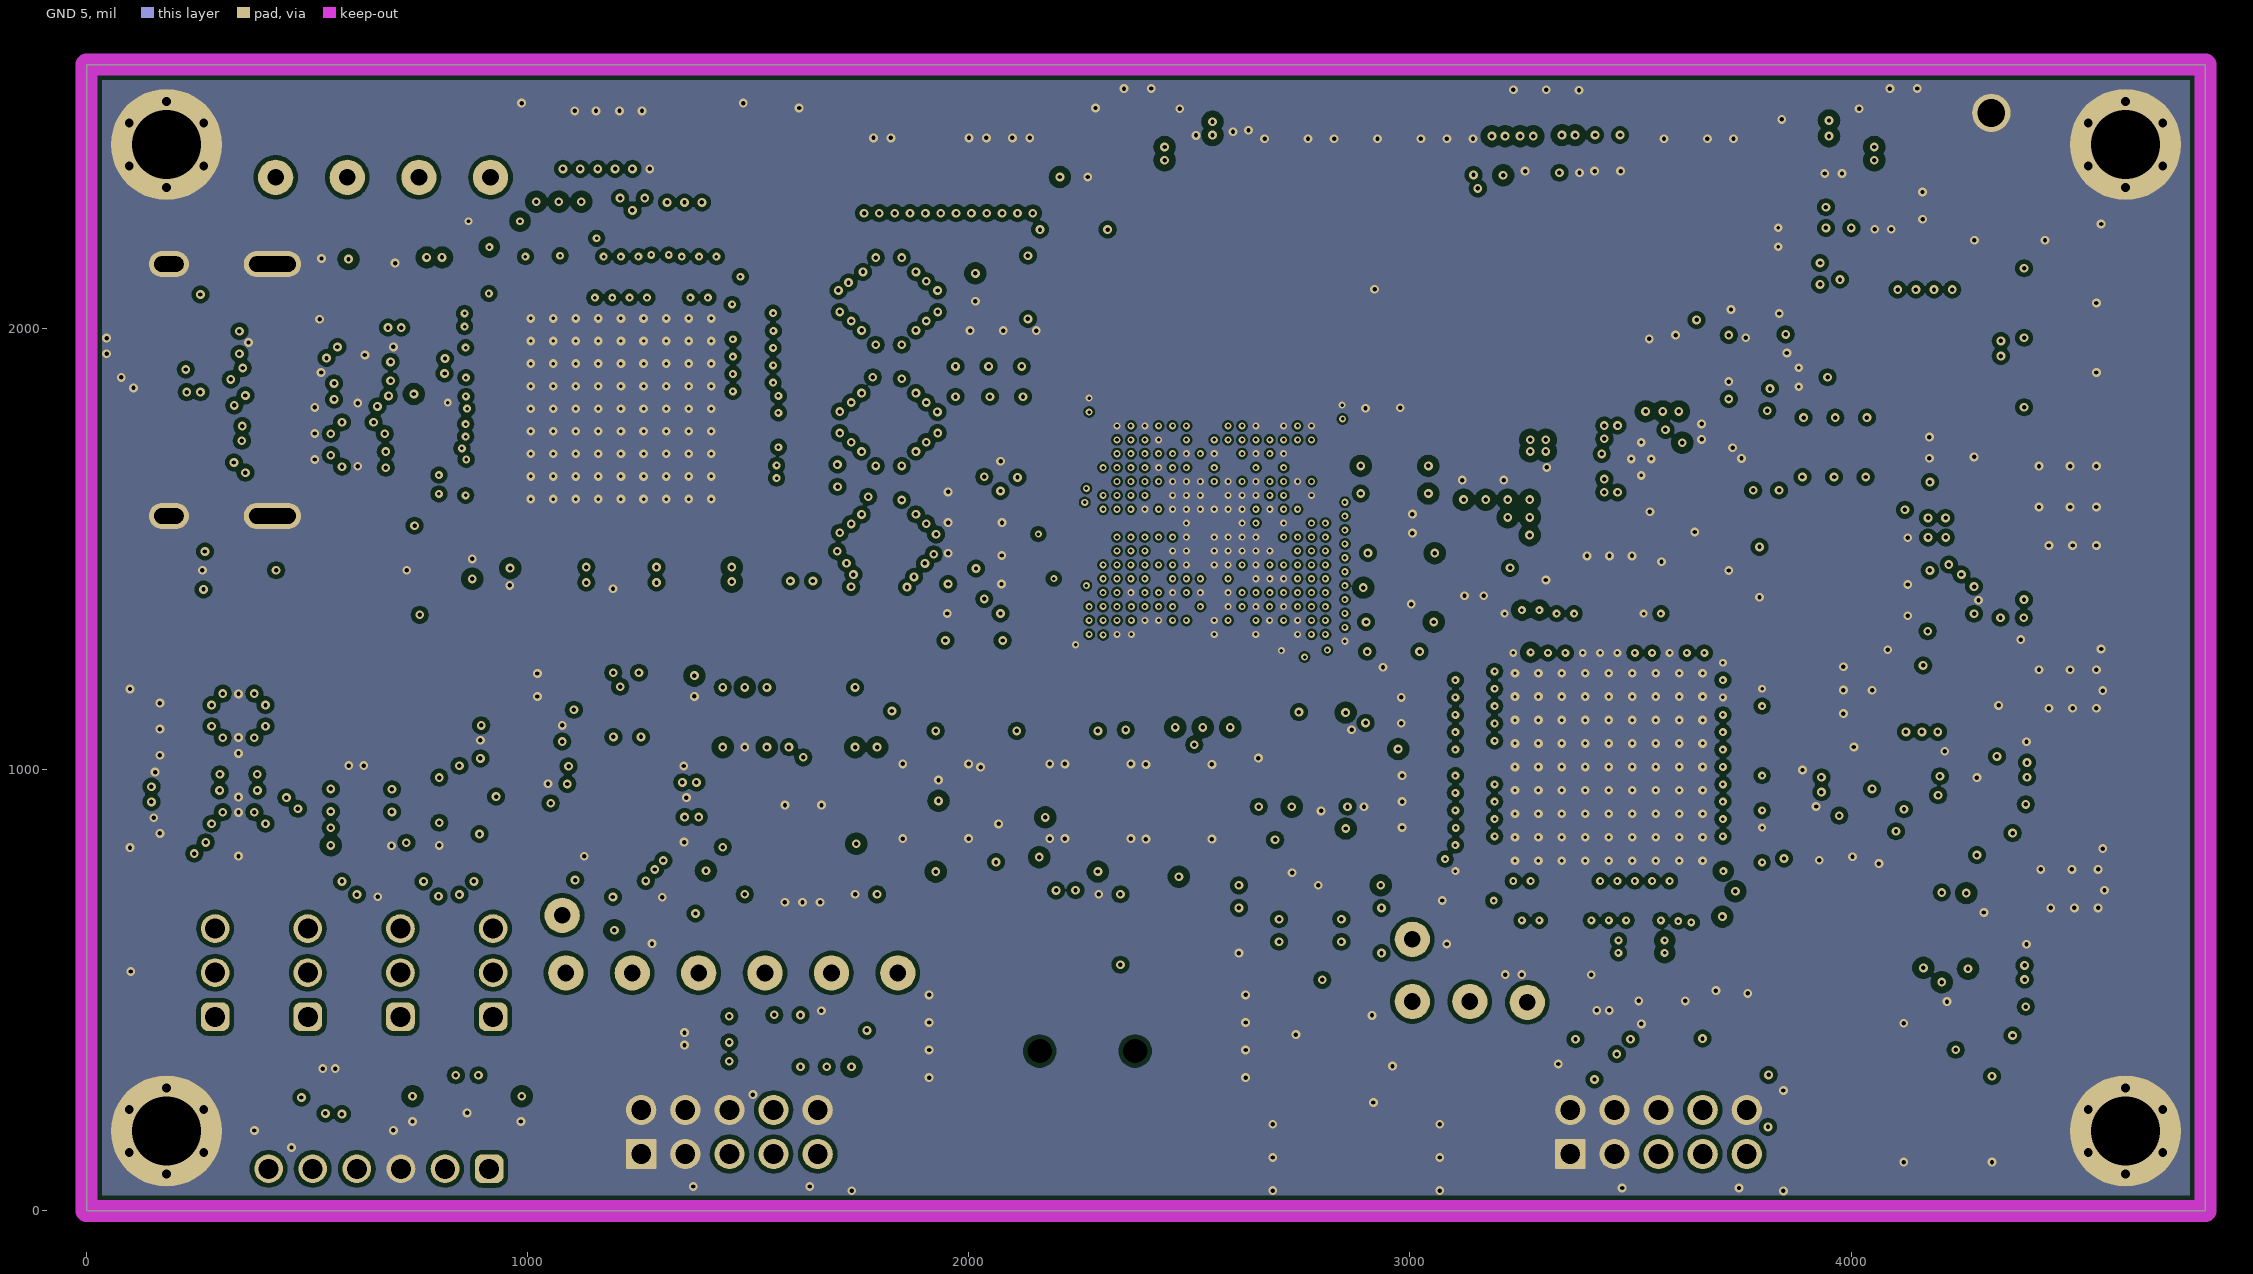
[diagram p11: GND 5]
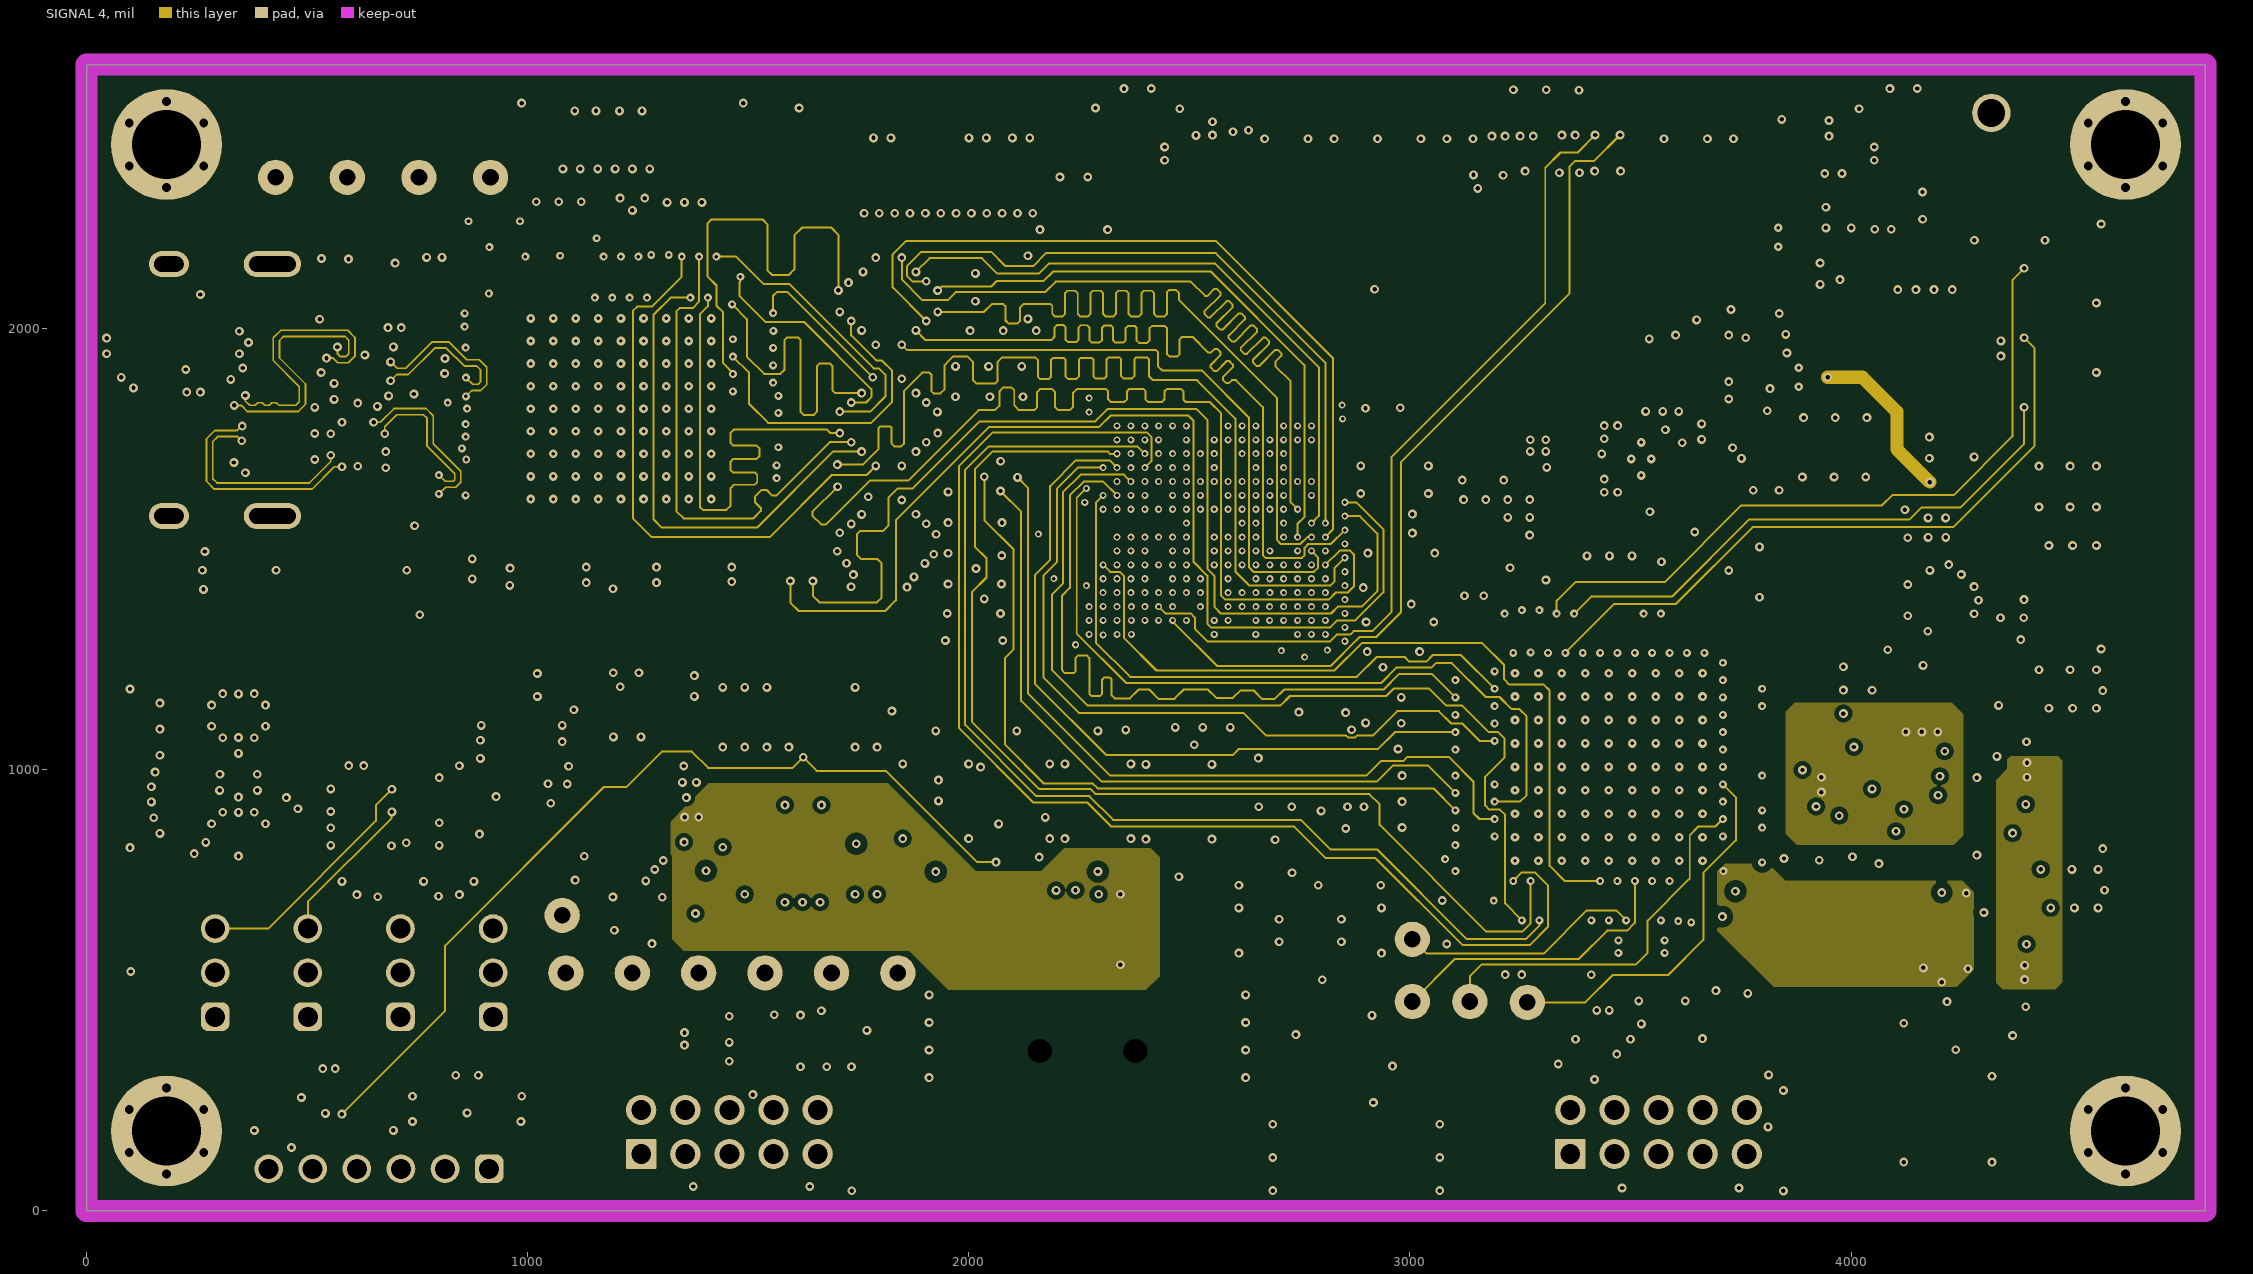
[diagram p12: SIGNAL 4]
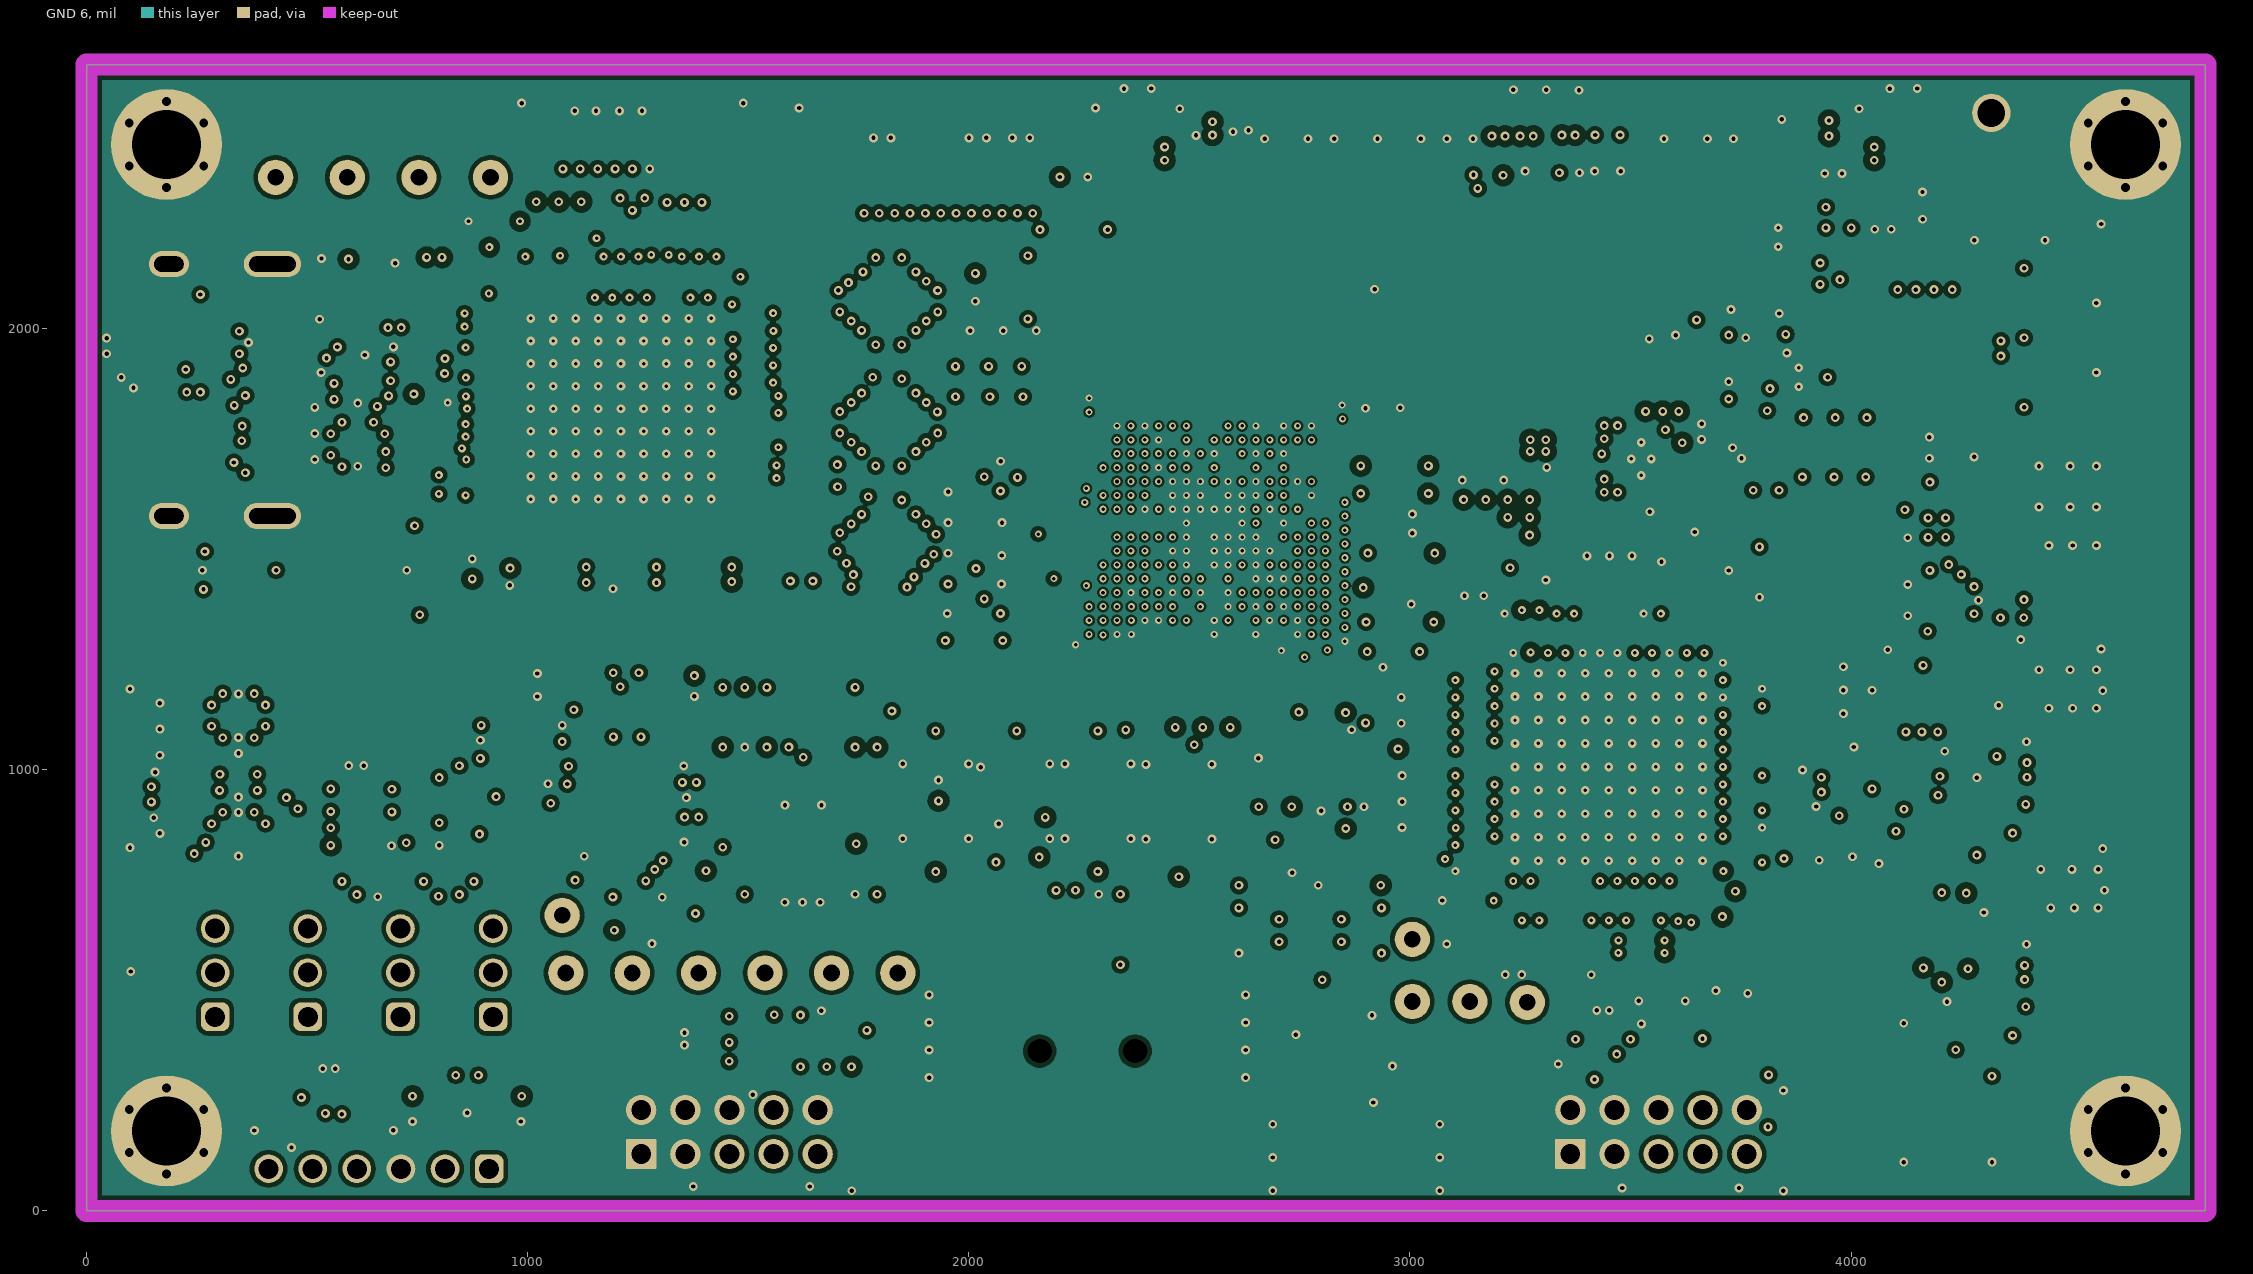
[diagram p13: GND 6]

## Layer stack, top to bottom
Top Solder: solder mask 0.8, Solder Resist, Dk 3.5
Top Layer: signal copper 2.1
Dielectric 1: prepreg 4, FR-4 High Tg, Dk 4.2
GND 1: signal copper 2.8
Dielectric 2: prepreg 6, FR-4 High Tg, Dk 4.2
SIGNAL 1: signal copper 1.4
Dielectric 3: prepreg 6, FR-4 High Tg, Dk 4.2
GND 2: signal copper 1.4
Dielectric 4: prepreg 6, FR-4 High Tg, Dk 4.2
SIGNAL 2: signal copper 1.4
Dielectric 5: prepreg 6, FR-4 High Tg, Dk 4.2
PWR SPLIT PLANE 1: signal copper 1.4
Dielectric 6: prepreg 4, FR-4 High Tg, Dk 4.1
GND 3: signal copper 1.4
Dielectric 7: core 3.6, FR-4 High Tg, Dk 4.2
GND 4: signal copper 1.4
Dielectric 8: prepreg 4, FR-4 High Tg, Dk 4.1
PWR SPLIT PLANE 2: signal copper 1.4
Dielectric 9: prepreg 6, FR-4 High Tg, Dk 4.2
SIGNAL 3: signal copper 1.4
Dielectric 10: prepreg 6, FR-4 High Tg, Dk 4.2
GND 5: signal copper 1.4
Dielectric 11: prepreg 6, FR-4 High Tg, Dk 4.2
SIGNAL 4: signal copper 1.4
Dielectric 12: prepreg 6, FR-4 High Tg, Dk 4.2
GND 6: signal copper 2.8
Dielectric 13: prepreg 4, FR-4 High Tg, Dk 4.2
Bottom Layer: signal copper 2.1
Bottom Solder: solder mask 0.8, Solder Resist, Dk 3.5

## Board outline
0,0 4803.15,0 4803.15,2598.43 0,2598.43

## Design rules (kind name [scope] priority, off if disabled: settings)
AcuteAngle [All] p1: minimum=4.50000000000000E+0001 checktracksonly=FALSE
AssemblyTestPointUsage [All] p1: valid=2
Clearance Clearance_FiducialMark [IsKeepOut and InComponentClass('FiducialMark') vs IsPad and InComponentClass('FiducialMark')] p1: gap=0 ignorepadtopadclearanceinfootprint=FALSE
Clearance Clearance_2 [IsKeepOut and InComponentClass('FiducialMark')] p2: gap=5.9 ignorepadtopadclearanceinfootprint=FALSE
Clearance Clearance_FiducialMark_1 [IsKeepOut and InComponentClass('FiducialMark')] p3: gap=5.9 ignorepadtopadclearanceinfootprint=FALSE
Clearance Clearance_1 [IsPad and not WithinRoom('RoomDefinition') vs IsVia and not InAnyComponent] p4: gap=0.5 ignorepadtopadclearanceinfootprint=FALSE
Clearance Clearance_Keepouts [((IsTrack Or IsArc) And Not InPoly) And IsFree and IsKeepOut vs ((IsTrack Or IsArc) And Not InPoly) And IsFree and IsKeepOut] p5: gap=0 ignorepadtopadclearanceinfootprint=FALSE
Clearance Clearance_Room [WithinRoom('RoomDefinition')] p6: gap=5 ignorepadtopadclearanceinfootprint=FALSE except(5.4: Arc-Arc Arc-Track Track-Track)
Clearance "Clearance_Voltage Spacing" [InNetClass('Voltage Spacing (15Mils)')] p7: gap=15 ignorepadtopadclearanceinfootprint=TRUE
Clearance "Clearance_Poly to Poly" [InPoly vs InPoly] p8: gap=15 ignorepadtopadclearanceinfootprint=FALSE
Clearance Clearance_Poly [InPolygon] p9: gap=10 ignorepadtopadclearanceinfootprint=FALSE
Clearance [All] p10: gap=5.9 ignorepadtopadclearanceinfootprint=FALSE
ComponentClearance ComponentClearance_MountingHoles_FiducialMarks [InComponentClass('Mounting Holes') vs InComponentClass('FiducialMark')] p1: gap=50 collisioncheckmode=3 verticalgap=10 showdistances=FALSE
ComponentClearance ComponentClearance_Shunt [InComponentClass('Header') vs InComponentClass('Shunt')] p2: gap=0 collisioncheckmode=3 verticalgap=0 showdistances=FALSE
ComponentClearance ComponentClearance_Logo [InComponentClass('Logo')] p3: gap=30 collisioncheckmode=3 verticalgap=10 showdistances=FALSE
ComponentClearance ComponentClearance_ScrewToNut [(HasFootprint('NY PMS 440 0025 PH')) vs (HasFootprint('Keystone_1902C'))] p4: gap=5 collisioncheckmode=3 verticalgap=10 showdistances=FALSE
ComponentClearance ComponentClearance_MountingHoles [InComponentClass('Mounting Holes')] p5: gap=100 collisioncheckmode=3 verticalgap=100000 showdistances=FALSE
ComponentClearance ComponentClearance_SmallPassives [HasFootprint('0201*') or HasFootprint('0402*') or HasFootprint('0508') or HasFootprint('0603*') or HasFootprint('0612') or HasFootprint('0805*') or HasFootprint('0815*') or HasFootprint('0830*') or HasFootprint('1206*') or HasFootprint('1210*') or HasFootprint('1808*') or HasFootprint('1812*') or HasFootprint('1825*') or HasFootprint('2010*') or HasFootprint('2220*') or HasFootprint('2225*') or HasFootprint('2512*') or HasFootprint('2728*') or HasFootprint('3518*') vs HasFootprint('0201*') or HasFootprint('0402*') or HasFootprint('0508') or HasFootprint('0603*') or HasFootprint('0612') or HasFootprint('0805*') or HasFootprint('0815*') or HasFootprint('0830*') or HasFootprint('1206*') or HasFootprint('1210*') or HasFootprint('1808*') or HasFootprint('1812*') or HasFootprint('1825*') or HasFootprint('2010*') or HasFootprint('2220*') or HasFootprint('2225*') or HasFootprint('2512*') or HasFootprint('2728*') or HasFootprint('3518*')] p6: gap=14.96 collisioncheckmode=3 verticalgap=10 showdistances=FALSE
ComponentClearance ComponentClearance_THtoSMT [IsThruComponent vs IsSMTComponent] p7: gap=24 collisioncheckmode=3 verticalgap=30 showdistances=FALSE
ComponentClearance ComponentClearance_THtoTH [IsThruComponent vs IsThruComponent] p8: gap=20 collisioncheckmode=3 verticalgap=30 showdistances=FALSE
ComponentClearance [All] p9: gap=15 collisioncheckmode=3 verticalgap=10 showdistances=FALSE
DiffPairsRouting DiffPairsRouting_90OHM [InNetClass('90OHM (USB)')] p1: maxlimit=14 minlimit=9 mostfreqgap=14 toplayer_mingap=14 toplayer_minwidth=7 toplayer_maxwidth=7 toplayer_prefwidth=7 midlayer1_mingap=14 midlayer1_minwidth=7 midlayer1_maxwidth=7 midlayer1_prefwidth=7 midlayer2_maxgap=9 midlayer2_prefgap=9 midlayer2_minwidth=5 midlayer2_maxwidth=5 midlayer2_prefwidth=5 midlayer3_mingap=14 midlayer3_minwidth=7 midlayer3_maxwidth=7 midlayer3_prefwidth=7 midlayer4_mingap=14 midlayer4_minwidth=7 midlayer4_maxwidth=7 midlayer4_prefwidth=7 midlayer5_maxgap=9 midlayer5_prefgap=9 midlayer5_minwidth=5 midlayer5_maxwidth=5 midlayer5_prefwidth=5 midlayer6_mingap=14 midlayer6_minwidth=7 midlayer6_maxwidth=7 midlayer6_prefwidth=7 midlayer7_maxgap=9 midlayer7_prefgap=9 midlayer7_minwidth=5 midlayer7_maxwidth=5 midlayer7_prefwidth=5 midlayer8_maxgap=9 midlayer8_prefgap=9 midlayer8_minwidth=5 midlayer8_maxwidth=5 midlayer8_prefwidth=5 midlayer9_mingap=14 midlayer9_minwidth=7 midlayer9_maxwidth=7 midlayer9_prefwidth=7 midlayer10_mingap=14 midlayer10_minwidth=7 midlayer10_maxwidth=7 midlayer10_prefwidth=7 midlayer11_mingap=14 midlayer11_minwidth=7 midlayer11_maxwidth=7 midlayer11_prefwidth=7 midlayer12_mingap=14 midlayer12_minwidth=7 midlayer12_maxwidth=7 midlayer12_prefwidth=7 bottomlayer_mingap=14 bottomlayer_minwidth=7 bottomlayer_maxwidth=7 bottomlayer_prefwidth=7 maxuncoupledlength=500
DiffPairsRouting "DiffPairsRouting_100OHM(DMD High Speed sub-LVDS)" [InDifferentialPairClass('100 OHM (DMD High Speed sub-LVDS)')] p2: maxlimit=11.4 minlimit=10 mostfreqgap=11.4 toplayer_mingap=11.4 toplayer_minwidth=5.4 toplayer_maxwidth=5.4 toplayer_prefwidth=5.4 midlayer1_mingap=11.4 midlayer1_minwidth=5.4 midlayer1_maxwidth=5.4 midlayer1_prefwidth=5.4 midlayer2_maxgap=10 midlayer2_prefgap=10 midlayer2_minwidth=4 midlayer2_maxwidth=4 midlayer2_prefwidth=4 midlayer3_mingap=11.4 midlayer3_minwidth=5.4 midlayer3_maxwidth=5.4 midlayer3_prefwidth=5.4 midlayer4_mingap=11.4 midlayer4_minwidth=5.4 midlayer4_maxwidth=5.4 midlayer4_prefwidth=5.4 midlayer5_maxgap=10 midlayer5_prefgap=10 midlayer5_minwidth=4 midlayer5_maxwidth=4 midlayer5_prefwidth=4 midlayer6_mingap=11.4 midlayer6_minwidth=5.4 midlayer6_maxwidth=5.4 midlayer6_prefwidth=5.4 midlayer7_maxgap=10 midlayer7_prefgap=10 midlayer7_minwidth=4 midlayer7_maxwidth=4 midlayer7_prefwidth=4 midlayer8_maxgap=10 midlayer8_prefgap=10 midlayer8_minwidth=4 midlayer8_maxwidth=4 midlayer8_prefwidth=4 midlayer9_mingap=11.4 midlayer9_minwidth=5.4 midlayer9_maxwidth=5.4 midlayer9_prefwidth=5.4 midlayer10_mingap=11.4 midlayer10_minwidth=5.4 midlayer10_maxwidth=5.4 midlayer10_prefwidth=5.4 midlayer11_mingap=11.4 midlayer11_minwidth=5.4 midlayer11_maxwidth=5.4 midlayer11_prefwidth=5.4 midlayer12_mingap=11.4 midlayer12_minwidth=5.4 midlayer12_maxwidth=5.4 midlayer12_prefwidth=5.4 bottomlayer_mingap=11.4 bottomlayer_minwidth=5.4 bottomlayer_maxwidth=5.4 bottomlayer_prefwidth=5.4 maxuncoupledlength=1000
DiffPairsRouting "DiffPairsRouting_100OHM(HDMI & LDI)" [InNetClass('100 OHM (HDMI Signals)') or InNetClass('100 OHM (Open LDI)')] p3: maxlimit=11.4 minlimit=10 mostfreqgap=11.4 toplayer_mingap=11.4 toplayer_minwidth=5.4 toplayer_maxwidth=5.4 toplayer_prefwidth=5.4 midlayer1_mingap=11.4 midlayer1_minwidth=5.4 midlayer1_maxwidth=5.4 midlayer1_prefwidth=5.4 midlayer2_maxgap=10 midlayer2_prefgap=10 midlayer2_minwidth=4 midlayer2_maxwidth=4 midlayer2_prefwidth=4 midlayer3_mingap=11.4 midlayer3_minwidth=5.4 midlayer3_maxwidth=5.4 midlayer3_prefwidth=5.4 midlayer4_mingap=11.4 midlayer4_minwidth=5.4 midlayer4_maxwidth=5.4 midlayer4_prefwidth=5.4 midlayer5_maxgap=10 midlayer5_prefgap=10 midlayer5_minwidth=4 midlayer5_maxwidth=4 midlayer5_prefwidth=4 midlayer6_mingap=11.4 midlayer6_minwidth=5.4 midlayer6_maxwidth=5.4 midlayer6_prefwidth=5.4 midlayer7_maxgap=10 midlayer7_prefgap=10 midlayer7_minwidth=4 midlayer7_maxwidth=4 midlayer7_prefwidth=4 midlayer8_maxgap=10 midlayer8_prefgap=10 midlayer8_minwidth=4 midlayer8_maxwidth=4 midlayer8_prefwidth=4 midlayer9_mingap=11.4 midlayer9_minwidth=5.4 midlayer9_maxwidth=5.4 midlayer9_prefwidth=5.4 midlayer10_mingap=11.4 midlayer10_minwidth=5.4 midlayer10_maxwidth=5.4 midlayer10_prefwidth=5.4 midlayer11_mingap=11.4 midlayer11_minwidth=5.4 midlayer11_maxwidth=5.4 midlayer11_prefwidth=5.4 midlayer12_mingap=11.4 midlayer12_minwidth=5.4 midlayer12_maxwidth=5.4 midlayer12_prefwidth=5.4 bottomlayer_mingap=11.4 bottomlayer_minwidth=5.4 bottomlayer_maxwidth=5.4 bottomlayer_prefwidth=5.4 maxuncoupledlength=500
DiffPairsRouting [All] p4: maxlimit=100 minlimit=10 mostfreqgap=10 toplayer_minwidth=15 toplayer_maxwidth=15 toplayer_prefwidth=15 midlayer1_minwidth=15 midlayer1_maxwidth=15 midlayer1_prefwidth=15 midlayer2_minwidth=15 midlayer2_maxwidth=15 midlayer2_prefwidth=15 midlayer3_minwidth=15 midlayer3_maxwidth=15 midlayer3_prefwidth=15 midlayer4_minwidth=15 midlayer4_maxwidth=15 midlayer4_prefwidth=15 midlayer5_minwidth=15 midlayer5_maxwidth=15 midlayer5_prefwidth=15 midlayer6_minwidth=15 midlayer6_maxwidth=15 midlayer6_prefwidth=15 midlayer7_minwidth=15 midlayer7_maxwidth=15 midlayer7_prefwidth=15 midlayer8_minwidth=15 midlayer8_maxwidth=15 midlayer8_prefwidth=15 midlayer9_minwidth=15 midlayer9_maxwidth=15 midlayer9_prefwidth=15 midlayer10_minwidth=15 midlayer10_maxwidth=15 midlayer10_prefwidth=15 midlayer11_minwidth=15 midlayer11_maxwidth=15 midlayer11_prefwidth=15 midlayer12_minwidth=15 midlayer12_maxwidth=15 midlayer12_prefwidth=15 bottomlayer_minwidth=15 bottomlayer_maxwidth=15 bottomlayer_prefwidth=15 maxuncoupledlength=1000
FabricationTestPointUsage TestPointUsage [All] p1: valid=2 allowmultiple=FALSE
FabricationTestpoint Testpoint [All] p1: side=3 testpointundercomponent=TRUE minsize=40 maxsize=100 preferedsize=60 minholesize=0 maxholesize=40 preferedholesize=32 testpointgrid=1 allowsidetop=TRUE allowsidebottom=TRUE usegrid=TRUE gridtolerance=0.01
FanoutControl Fanout_LCC [IsLCC] p1: bgadir=Out bgaviamode=Centered fanoutstyle=Auto fanoutdirection=Alternating viagrid=1 // Fanout_LCC (Default Rule)
FanoutControl Fanout_BGA [IsBGA] p2: bgadir=Out bgaviamode=Centered fanoutstyle=Auto fanoutdirection=Alternating viagrid=1 // Fanout_BGA (Default Rule)
FanoutControl Fanout_Default [All] p4: bgadir=Out bgaviamode=Centered fanoutstyle=Auto fanoutdirection=Alternating viagrid=1 // Fanout_Default (Default Rule)
FanoutControl Fanout_Small [(CompPinCount < 5)] p5: bgadir=Out bgaviamode=Centered fanoutstyle=Auto fanoutdirection=OutThenIn viagrid=1 // Fanout_Small (Default Rule)
HoleSize [All] p1: absolutevalues=TRUE maxlimit=251 minlimit=7.87 maxpercent=80.000 minpercent=20.000
HoleToHoleClearance HoleToHoleClearance_1 [HasFootprint('MTGP_252mil_157mil_6Via') vs IsVia] p1: gap=0 allowstackedmicrovias=TRUE
HoleToHoleClearance [All] p2: gap=10 allowstackedmicrovias=TRUE
MinimumAnnularRing MinimumAnnularRing_ThermalPadVias [IsVia and InAnyComponent] p1: minimumring=5.91
MinimumAnnularRing [All] p2: minimumring=4
MinimumSolderMaskSliver MinimumSolderMaskSliver_Logo [InComponentClass('Logo') vs InComponentClass('Logo')] p1: minsoldermaskwidth=0.7
MinimumSolderMaskSliver [All] p2: minsoldermaskwidth=3.94
PlaneConnect PlaneConnect_PWR [InNetClass('POWER')] p1: planeconnectstyle=Direct reliefexpansion=20 reliefentries=4 reliefconductorwidth=10 reliefairgap=10
PlaneConnect [All] p2: pad.planeconnectstyle=Relief pad.reliefexpansion=15 pad.reliefentries=4 pad.reliefconductorwidth=10 pad.reliefairgap=10 via.planeconnectstyle=Direct via.reliefexpansion=10 via.reliefentries=4 via.reliefconductorwidth=10 via.reliefairgap=10
PolygonConnect PolygonConnect_PWR [InNetClass('POWER')] p1: connectstyle=Direct reliefconductorwidth=10 reliefentries=4 polygonreliefangle="90 Angle" airgapwidth=10
PolygonConnect [All] p2: thpad.connectstyle=Relief thpad.reliefconductorwidth=15 thpad.reliefentries=4 thpad.polygonreliefangle="90 Angle" thpad.airgapwidth=10 smdpad.connectstyle=Direct smdpad.reliefconductorwidth=15 smdpad.reliefentries=4 smdpad.polygonreliefangle="90 Angle" smdpad.airgapwidth=10 via.connectstyle=Direct via.reliefconductorwidth=10 via.reliefentries=4 via.polygonreliefangle="90 Angle" via.airgapwidth=10
RoomDefinition controller_video [InComponentClass('controller_video')] p1: confinementstyle=ConfineIn formatcopy=TRUE lockcomponents=FALSE outline -692,-1534 1308,-1534 1308,-534 -692,-534
RoomDefinition controller_TPS99000 [InComponentClass('controller_TPS99000')] p2: confinementstyle=ConfineIn formatcopy=TRUE lockcomponents=FALSE outline -692,-1534 1308,-1534 1308,-534 -692,-534
RoomDefinition controller_host_connections [InComponentClass('controller_host_connections')] p3: confinementstyle=ConfineIn formatcopy=TRUE lockcomponents=FALSE outline -692,-1534 1308,-1534 1308,-534 -692,-534
RoomDefinition controller_DMD_interface [InComponentClass('controller_DMD_interface')] p4: confinementstyle=ConfineIn formatcopy=TRUE lockcomponents=FALSE outline -692,-1534 1308,-1534 1308,-534 -692,-534
RoomDefinition "controller_dlpc230 power and clock" [InComponentClass('controller_dlpc230 power and clock')] p5: confinementstyle=ConfineIn formatcopy=TRUE lockcomponents=FALSE outline -692,-1534 1308,-1534 1308,-534 -692,-534
RoomDefinition controller_configuration [InComponentClass('controller_configuration')] p6: confinementstyle=ConfineIn formatcopy=TRUE lockcomponents=FALSE outline -692,-1534 1308,-1534 1308,-534 -692,-534
RoomDefinition controller_system_power [InComponentClass('controller_system_power')] p7: confinementstyle=ConfineIn formatcopy=TRUE lockcomponents=FALSE outline 2229.36,1881.97 2879.39,1881.97 2879.39,1236.24 2229.36,1236.24
RoutingLayers RoutingLayers_1 [InNetClass('100 OHM (DMD High Speed sub-LVDS)')] p1: top layer_v5=TRUE mid layer 1_v5=FALSE mid layer 2_v5=TRUE mid layer 3_v5=FALSE mid layer 4_v5=FALSE mid layer 5_v5=TRUE mid layer 6_v5=FALSE mid layer 7_v5=TRUE mid layer 8_v5=TRUE mid layer 9_v5=TRUE mid layer 10_v5=TRUE mid layer 11_v5=TRUE mid layer 12_v5=TRUE bottom layer_v5=TRUE
RoutingLayers [All] p2: top layer_v5=TRUE mid layer 1_v5=FALSE mid layer 2_v5=TRUE mid layer 3_v5=FALSE mid layer 4_v5=FALSE mid layer 5_v5=TRUE mid layer 6_v5=FALSE mid layer 7_v5=TRUE mid layer 8_v5=TRUE mid layer 9_v5=FALSE mid layer 10_v5=FALSE mid layer 11_v5=FALSE mid layer 12_v5=FALSE bottom layer_v5=TRUE
RoutingVias ThermalPadVias [IsVia and InAnyComponent] p1: holewidth=7.87 width=19 viastyle="Through Hole" minholewidth=7.87 minwidth=19.68 maxholewidth=20 maxwidth=40
RoutingVias [All] p2: holewidth=16 width=34 viastyle="Through Hole" minholewidth=8 minwidth=16 maxholewidth=40 maxwidth=65
SilkToBoardRegionClearance [Not ((IsComment or IsDesignator) And (Hide <> 'False')) and not InRegion(1000,500,4000,800)] p1:
SilkToSilkClearance SilkToSilkClearance_Pb-FreeLogo [(HasFootprint('Pb-Free_Overlay_Medium') OR HasFootprint('Pb-Free_Overlay_Small')) vs (HasFootprint('Pb-Free_Overlay_Medium') OR HasFootprint('Pb-Free_Overlay_Small'))] p1: silktosilkclearance=0
SilkToSilkClearance [All] p2: silktosilkclearance=3.94
SilkToSolderMaskClearance SilkToComponentPadClearance [(IsPad or IsFill or IsRegion) and InAnycomponent] p1: minsilkscreentomaskgap=5 clearancetoexposedcopper=TRUE
SilkToSolderMaskClearance "Silk to Solder Mask Opening" [All] p2: minsilkscreentomaskgap=3.94 clearancetoexposedcopper=FALSE
SolderMaskExpansion [HasFootprint('FP-702461002_HDR10-MFG')] p1: expansion=2 istentingtop=FALSE
SolderMaskExpansion SolderMaskExpansion_1 [All] p2: expansion=0 istentingtop=FALSE
UnRoutedNet [All] p1: checkbadconnections=TRUE
Width "Width_50 OHM" [InNetClass('50OHM')] p1: maxlimit=6.3 minlimit=4.5 preferedwidth=6.3 toplayer_minwidth=5 midlayer1_minwidth=5 midlayer2_maxwidth=4.5 midlayer2_prefwidth=4.5 midlayer3_minwidth=5 midlayer4_minwidth=5 midlayer5_maxwidth=4.5 midlayer5_prefwidth=4.5 midlayer6_minwidth=5 midlayer7_maxwidth=4.5 midlayer7_prefwidth=4.5 midlayer8_maxwidth=4.5 midlayer8_prefwidth=4.5 midlayer9_minwidth=5 midlayer10_minwidth=5 midlayer11_minwidth=5 midlayer12_minwidth=5 bottomlayer_minwidth=5 minimp=50.000000 maximp=50.000000 favimp=50.000000
Width [All] p2: maxlimit=100 minlimit=4 preferedwidth=10 checkconnectedcopper=TRUE
12 further rules are at their usual default settings.

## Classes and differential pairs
differential pair class "100 OHM (DMD High Speed sub-LVDS)": DMD_LS0_CLK DMD_LS0_WDATA HS_A_CLK HS_A_WDATA0 HS_A_WDATA1 HS_A_WDATA2 HS_A_WDATA3 HS_A_WDATA4 HS_A_WDATA5 HS_A_WDATA6 HS_A_WDATA7 HS_B_CLK HS_B_WDATA0 HS_B_WDATA1 HS_B_WDATA2 HS_B_WDATA3 HS_B_WDATA4 HS_B_WDATA5 HS_B_WDATA6 HS_B_WDATA7
net class "Voltage Spacing (15Mils)": DMD_VBIAS DMD_VOFS DMD_VRST P1P1V P1P8V P3P3V VCC3IO_COSC
net class POWER: CY_VBUS DVI_5V GND NetC26_1 NetC38_1 NetC38_2 NetC48_1 NetC561_1 NetC587_1 NetD1_2 NetL518_1 NetL520_1 NetR9_1 NetR500_1 P1P1V P1P8V P3P3V P3P3V_REG P3P3V_TPS99K P6P5V P6P5V_F SPI0_DIR1 V_DVI_AVDD V_DVI_DVDD V_DVI_OVDD V_DVI_PVDD VCC11A_DDI VCC11A_LVDS VCC18A_LVDS VIN VIN_MAIN
net class "100 OHM (Open LDI)": L1_CLK_N L1_CLK_N_S L1_CLK_P L1_CLK_P_S L1_DATA0_N L1_DATA0_N_S L1_DATA0_P L1_DATA0_P_S L1_DATA1_N L1_DATA1_N_S L1_DATA1_P L1_DATA1_P_S L1_DATA2_N L1_DATA2_N_S L1_DATA2_P L1_DATA2_P_S L1_DATA3_N L1_DATA3_N_S L1_DATA3_P L1_DATA3_P_S
net class "100 OHM (HDMI Signals)": RXCLK_N RXCLK_N_S RXCLK_P RXCLK_P_S RXIN0_N RXIN0_N_S RXIN0_P RXIN0_P_S RXIN1_N RXIN1_N_S RXIN1_P RXIN1_P_S RXIN2_N RXIN2_N_S RXIN2_P RXIN2_P_S
net class "100 OHM (DMD High Speed sub-LVDS)": DMD_LS0_CLK_N DMD_LS0_CLK_P DMD_LS0_WDATA_N DMD_LS0_WDATA_P HS_A_CLK_N HS_A_CLK_P HS_A_WDATA0_N HS_A_WDATA0_P HS_A_WDATA1_N HS_A_WDATA1_P HS_A_WDATA2_N HS_A_WDATA2_P HS_A_WDATA3_N HS_A_WDATA3_P HS_A_WDATA4_N HS_A_WDATA4_P HS_A_WDATA5_N HS_A_WDATA5_P HS_A_WDATA6_N HS_A_WDATA6_P HS_A_WDATA7_N HS_A_WDATA7_P HS_B_CLK_N HS_B_CLK_P HS_B_WDATA0_N HS_B_WDATA0_P HS_B_WDATA1_N HS_B_WDATA1_P HS_B_WDATA2_N HS_B_WDATA2_P HS_B_WDATA3_N HS_B_WDATA3_P HS_B_WDATA4_N HS_B_WDATA4_P HS_B_WDATA5_N HS_B_WDATA5_P HS_B_WDATA6_N HS_B_WDATA6_P HS_B_WDATA7_N HS_B_WDATA7_P
net class "90OHM (USB)": USBDM USBDP
net class 50OHM: AMUX0 AMUX1 BLUE_LED_THERM CHKSUM_SEL CKS_PU CY_GPIO_7 CY_GPIO_11 CY_GPIO_12 CY_GPIO_13 CY_HOST_I2C_OE CY_HOST_SCL CY_HOST_SDA CY_SPI_CLK CY_SPI_CSZ CY_SPI_PICO CY_SPI_POCI DA_M_S DATAEN DATAEN_S DDC_clock DDC_data DLPC230_RESETZ DMD_DEN_ARSTZ DMD_LS0_RDATA DMD_LS1_RDATA DMUX0 DMUX1 DRST_SB FAN_PWM GND11AD_PLLD GND11AD_PLLM GPIO_9 GPIO_10 GPIO_11 GPIO_12 GPIO_13 GPIO_14 GPIO_19 GPIO_20 GPIO_22 GPIO_23 GPIO_24 GPIO_25 GREEN_LED_THERM HOLD_BOOT_H HOLD_BOOTZ HOST1_SPI_CLK HOST1_SPI_CLK_S HOST1_SPI_CSZ HOST1_SPI_CSZ_S HOST1_SPI_PICO HOST1_SPI_POCI HOST2_SPI_CLK HOST2_SPI_CLK_S HOST2_SPI_CSZ HOST2_SPI_CSZ_S HOST2_SPI_PICO HOST2_SPI_PICO_S HOST2_SPI_POCI HOST_I2C_SCL HOST_I2C_SDA HOST_IF_SEL HOST_IRQ HOST_IRQ_S HOST_SPI_CLK HOST_SPI_CSZ HOST_SPI_MODE HOST_SPI_PICO HOST_SPI_POCI HOST_SPI_POCI_S HOTPLUGDETECT HSEL_PU HSYNC HSYNC_S HUD_LEDSEL_0 HUD_LEDSEL_1 HUD_LEDSEL_2 HUD_LEDSEL_3 JTAGRSTZ L1_CLK_N L1_CLK_P L1_DATA0_N L1_DATA0_P L1_DATA1_N L1_DATA1_P L1_DATA2_N L1_DATA2_P L1_DATA3_N L1_DATA3_P LED_ANODE_DIVIDED LED_ANODE_DIVIDED_F MSTR_SCL MSTR_SDA N8V_FIL NetC12_1 NetC619_1 NetR4_2 NetR14_1 NetR42_1 NetR43_1 NetR44_1 NetR45_1 NetR58_1 NetR59_1 NetR62_2 NetR63_2 NetR513_1 NetR517_2 NetR540_1 NetR572_1 NetTP5_1 NetTP7_1 NetU2_U1 NetU13_4 P1P1V_EN P1P8V_EN P3P3V_EN PCLK PCLK_S PDATA0 PDATA1 PDATA2 PDATA3 PDATA4 PDATA5 PDATA6 PDATA7 PDATA8 PDATA9 PDATA10 PDATA11 PDATA12 PDATA13 PDATA14 PDATA15 PDATA16 PDATA17 PDATA18 PDATA19 PDATA20 PDATA21 PDATA22 PDATA23 PDATA_S0 PDATA_S1 PDATA_S2 PDATA_S3 PDATA_S4 PDATA_S5 PDATA_S6 PDATA_S7 PDATA_S8 PDATA_S9 PDATA_S10 PDATA_S11 PDATA_S12 PDATA_S13 PDATA_S14 PDATA_S15 PDATA_S16 PDATA_S17 PDATA_S18 PDATA_S19 PDATA_S20 PDATA_S21 PDATA_S22 PDATA_S23 PLL_REF_C PLL_REFCLK_I PLL_REFCLK_O PMIC_AD3_PICO PMIC_AD3_POCI PMIC_AD3_SEQ_CLK PMIC_ADC_IN2 PMIC_ADC_IN3 PMIC_ADC_IN4 PMIC_BEN PMIC_BEN_F PMIC_CMODE PMIC_CMODE_F PMIC_COMPOUT PMIC_EXT_SMPL PMIC_GEN PMIC_GEN_F PMIC_INTZ PMIC_LED_DEN PMIC_LED_DEN_S PMIC_LED_SEN PMIC_LED_SEN_S PMIC_LEDSEL_0 PMIC_LEDSEL_0_S PMIC_LEDSEL_1 PMIC_LEDSEL_1_S PMIC_LEDSEL_2 PMIC_LEDSEL_2_S PMIC_LEDSEL_3 PMIC_LEDSEL_3_s PMIC_LM3409_DRVEN PMIC_LM3409_DRVEN_F PMIC_LM3409_IADJ PMIC_LM3409_IADJ_F PMIC_LM3409_SYNC PMIC_LM3409_SYNC_F PMIC_LS_SENSE_N PMIC_LS_SENSE_N_F PMIC_LS_SENSE_P PMIC_LS_SENSE_P_F PMIC_PARKZ PMIC_R_IADJ PMIC_REN PMIC_REN_F PMIC_SEN1 PMIC_SEN1_F PMIC_SEN2 PMIC_SEN2_F PMIC_SEQ_STRT PMIC_SEQ_STRT_S PMIC_SPI2_CLK PMIC_SPI2_CLK_S PMIC_SPI2_CSZ PMIC_SPI2_CSZ0 PMIC_SPI2_CSZ_S PMIC_SPI2_PICO PMIC_SPI2_POCI PMIC_SPI_CLK PMIC_SPI_CSZ0 PMIC_SPI_PICO PMIC_SPI_POCI PMIC_TIA_PD1 PMIC_TIA_PD1_FILT PMIC_TIA_PD2 PMIC_TIA_PD2_FILT PMIC_WD1 PMIC_WD1_S PROJ_ON PWM0_DVR_EN_S PWM0_OUT_DRV_EN_IN PWM0_OUT_F PWM1_COMPOUT_S PWM1_OUT_COMPOUT_IN PWM1_OUT_F PWM2_OUT PWM2_OUT_F RED_LED_THERM RPI_0 RPI_1 RPI_LS SPIMD_PU TESTPT0 TESTPT1 TESTPT2 TESTPT3 TESTPT5 TESTPT6 TP5_PU VCC11AD_PLLD VCC11AD_PLLM VRESET_FIL VSYNC VSYNC_S
component class controller_video: C3 C6 C7 C8 C10 C11 C13 C14 C15 C16 C20 C21 C22 C25 C28 C29 C30 C33 C517 C522 C528 C572 C573 J4 J6 L1 L3 L4 L514 R1 R2 R3 R15 R17 R501 R502 R503 R507 R515 R518 R538 R539 RN1 RN2 RN3 TP1 TP2 TP3 TP4 U2 U501 U502 U503 U505 U506 U507 U509 U511
component class controller_TPS99000: C34 C39 C43 C45 C46 C47 C48 C49 C50 C52 C53 C54 C55 C59 C506 C507 C508 C509 C510 C514 C515 C520 C523 C565 C589 C590 C591 C592 C594 C595 C599 C600 C601 C602 C604 C607 C608 C609 C610 C611 C612 C613 C615 C616 C617 C619 C624 C627 C628 D5 D6 FB1 FB2 FB3 FB500 J2 J3 J7 J8 J16 J500 L6 L7 L8 L500 L501 L502 L503 L504 L505 L506 L507 L508 L509 L510 L511 L525 L526 Q1 R6 R7 R8 R10 R11 R12 R19 R26 R27 R28 R29 R30 R35 R36 R41 R47 R50 R52 R54 R55 R57 R61 R62 R504 R506 R510 R511 R512 R519 R521 R522 R523 R529 R530 R532 R546 R559 R561 R562 R563 R565 R566 R569 R570 R573 R574 R575 R576 R577 R578 R579 R585 R586 R587 R588 R589 R590 R591 S SW6 TP6 TP13 TP14 TP15 U6 U9 U10 U13 U14 U513
component class controller_system_power: C2 C12 C17 C18 C19 C23 C26 C27 C31 C37 C38 C41 C512 C513 C516 C519 C525 C526 C535 C536 C537 C559 C561 C571 C587 D1 D2 D3 D4 J5 L2 L5 L516 L518 L520 R4 R5 R9 R13 R14 R16 R20 R21 R24 R25 R31 R32 R34 R500 R505 R508 R513 R514 R516 R517 R524 R534 R535 R540 R541 R544 TP17 U1 U3 U4 U5 U500 U504
component class controller_host_connections: C40 C42 C44 C51 C57 C58 C593 C596 C597 C603 C605 C606 C614 C618 C620 C621 C622 C623 C625 C626 J9 J10 J11 J12 J13 J15 J17 MH1 MH2 MH3 MH4 R39 R40 R42 R43 R44 R45 R46 R48 R49 R51 R53 R56 R58 R59 R60 R65 R551 R555 R560 R564 R567 R568 R572 R580 R581 R582 R583 R584 R592 R593 TP5 TP7 U7 U8 U11 U12 U15 U16 U17 U508 U512
component class controller_DMD_interface: C500 C501 C502 C503 C504 C505 C511 "ESD Susceptible1" FID1 FID2 FID3 FID4 FID5 FID6 J1 Logo1 Logo2 Logo3 Logo4 R526 R554 R558 ZZ1 ZZ2 ZZ3 ZZ4 ZZ5
component class "controller_dlpc230 power and clock": C1 C4 C5 C9 C24 C32 C35 C36 C518 C521 C524 C527 C529 C530 C531 C532 C533 C534 C538 C539 C540 C541 C542 C543 C544 C545 C546 C547 C548 C549 C550 C551 C552 C553 C554 C555 C556 C557 C558 C560 C562 C563 C564 C566 C567 C568 C569 C570 C574 C575 C576 C577 C578 C579 C580 C581 C582 C583 C584 C585 C586 C588 L512 L513 L515 L517 L519 L521 L522 L523 L524 R509 R520 R525 R527 R528 TP16 Y500
component class controller_configuration: C56 C598 J14 R18 R22 R23 R33 R37 R38 R63 R64 R531 R533 R536 R537 R542 R543 R545 R547 R548 R549 R550 R552 R553 R556 R557 R571 SW1 SW2 SW3 SW4 SW5 TP8 TP9 TP10 TP11 TP12 U510
differential pair HS_B_WDATA7: +HS_B_WDATA7_P -HS_B_WDATA7_N
differential pair HS_B_WDATA6: +HS_B_WDATA6_P -HS_B_WDATA6_N
differential pair HS_B_WDATA5: +HS_B_WDATA5_P -HS_B_WDATA5_N
differential pair HS_B_WDATA4: +HS_B_WDATA4_P -HS_B_WDATA4_N
differential pair HS_B_WDATA3: +HS_B_WDATA3_P -HS_B_WDATA3_N
differential pair HS_B_WDATA2: +HS_B_WDATA2_P -HS_B_WDATA2_N
differential pair HS_B_WDATA1: +HS_B_WDATA1_P -HS_B_WDATA1_N
differential pair HS_B_WDATA0: +HS_B_WDATA0_P -HS_B_WDATA0_N
differential pair HS_B_CLK: +HS_B_CLK_P -HS_B_CLK_N
differential pair HS_A_WDATA6: +HS_A_WDATA6_P -HS_A_WDATA6_N
differential pair HS_A_WDATA5: +HS_A_WDATA5_P -HS_A_WDATA5_N
differential pair HS_A_WDATA4: +HS_A_WDATA4_P -HS_A_WDATA4_N
differential pair HS_A_WDATA3: +HS_A_WDATA3_P -HS_A_WDATA3_N
differential pair HS_A_WDATA2: +HS_A_WDATA2_P -HS_A_WDATA2_N
differential pair HS_A_WDATA1: +HS_A_WDATA1_P -HS_A_WDATA1_N
differential pair HS_A_WDATA0: +HS_A_WDATA0_P -HS_A_WDATA0_N
differential pair HS_A_CLK: +HS_A_CLK_P -HS_A_CLK_N
differential pair DMD_LS0_WDATA: +DMD_LS0_WDATA_P -DMD_LS0_WDATA_N
differential pair DMD_LS0_CLK: +DMD_LS0_CLK_P -DMD_LS0_CLK_N
differential pair HS_A_WDATA7: +HS_A_WDATA7_P -HS_A_WDATA7_N

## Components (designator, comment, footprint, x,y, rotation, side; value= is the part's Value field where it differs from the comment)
C1 "CGA1A2X7R1A103K030BA" 0201_033 2237.13,2311.38 r0 top locked value=0.01uF
C2 "C1206C106J3RACAUTO" 1206_180 4051.03,2278.31 r0 top locked value=10uF
C3 "GCM155R71C104KA55D" 0402 924.11,2243.36 r180 top locked value=0.1uF
C4 "GCM188R71C105KA64D" 0603 2237.97,2224.42 r0 top locked value=1uF
C5 "GCM188R71C105KA64D" 0603 2133.94,2093.59 r270 top locked value=1uF
C6 "CL05C220JB5NNNC" 0402 532.56,2099.5 r90 top locked value=22pF
C7 "GCM155R71C104KA55D" 0402 1073.52,2093.91 r270 top locked value=0.1uF
C8 "GCM155R71C104KA55D" 0402 1309.74,2093.91 r270 top locked value=0.1uF
C9 "CGA1A2X7R1A103K030BA" 0201_033 2046.98,2094.42 r270 top locked value=0.01uF
C10 "GCM155R71C104KA55D" 0402 1486.91,2016.41 r180 top locked value=0.1uF
C11 "GCM155R71C104KA55D" 0402 935.72,2015.17 r0 top locked value=0.1uF
C12 "GCM1555C1H681FA16D" 0402 3510.7,1953.08 r90 top locked value=680pF
C13 "GCM155R71C104KA55D" 0402 935.72,1956.11 r0 top locked value=0.1uF
C14 "GCM155R71C104KA55D" 0402 935.72,1818.32 r0 top locked value=0.1uF
C15 "GCM155R71C104KA55D" 0402 1486.91,1818.32 r180 top locked value=0.1uF
C16 "GCM188R70J225KE22D" 0603 817.87,1759.37 r90 top locked value=2.2uF
C17 "GCM31CR70J226KE23L" 1206_180 3710.96,1699.91 r90 top locked value=22uF
C18 "GCM31CR70J226KE23L" 1206_180 3857.58,1729.88 r180 top locked value=22uF
C19 "GCM31CR70J226KE23L" 1206_180 4068.77,1729.87 r0 top locked value=22uF
C20 "GCM155R71C104KA55D" 0402 935.72,1739.58 r0 top locked value=0.1uF
C21 "GCM155R71C104KA55D" 0402 1486.91,1719.89 r180 top locked value=0.1uF
C22 "GCM155R71C104KA55D" 0402 935.72,1680.52 r0 top locked value=0.1uF
C23 "CGA6P3X7R1H475M250AB" 1210_280 4278.79,1602.5 r90 top locked value=4.7uF
C24 "CGA4J1X7R0J106K125AC" FP-CGA4J1X7R0J106K125AC_0805-MFG 2963.52,1626.13 r180 top locked value=10µF
C25 "GCM155R71C104KA55D" 0402 935.72,1622.06 r0 top locked value=0.1uF
C26 "CGA3E2C0G1H330J080AA" FP-CGA3E2C0G1H330J080AA_0603-MFG 3792.3,1562.32 r90 top locked value=33pF
C27 "GCM31CR70J226KE23L" 1206_180 3145.36,1507.47 r270 top locked value=22uF
C28 "GCM155R71C104KA55D" 0402 1132.58,1542.73 r90 top locked value=0.1uF
C29 "GCM155R71C104KA55D" 0402 1334.94,1542.73 r90 top locked value=0.1uF
C30 "GCM155R71C104KA55D" 0402 1414.94,1542.72 r90 top locked value=0.1uF
C31 "C0603C223K1RACAUTO" FP-C0603C223K1RACAUTO_0603-MFG 4155.63,1488.16 r0 top locked value=22pF
C32 "GCM188R70J225KE22D" 0603 2973.85,1491.04 r0 top locked value=2.2uF
C33 "GCM155R71C104KA55D" 0402 912.01,1456.29 r90 top locked value=0.1uF
C34 "GCM188R70J225KE22D" 0603 3607.86,1439.86 r90 top locked value=2.2uF
C35 "CGA4J1X7R0J106K125AC" FP-CGA4J1X7R0J106K125AC_0805-MFG 2966.47,1413.65 r180 top locked value=10µF
C36 "GCM188R70J225KE22D" 0603 2973.85,1334.92 r0 top locked value=2.2uF
C37 "C0603C223K1RACAUTO" FP-C0603C223K1RACAUTO_0603-MFG 4139.69,1272.09 r0 top locked value=22pF
C38 "GCM21BR72A104KA37L" 0805_HV 4288.18,1265.01 r0 top locked value=0.1uF
C39 "GCM188R70J225KE22D" 0603 3882.33,1222.85 r0 top locked value=2.2uF
C40 "GCM155R71C104KA55D" 0402 1348.1,1189.72 r270 top locked value=0.1uF
C41 "CGA6P3X7R1H475M250AB" 1210_280 4227.76,1145.81 r0 top locked value=4.7uF
C42 "GCM155R71C104KA55D" 0402 1080.18,1166 r180 top locked value=0.1uF
C43 "GCM188R70J225KE22D" 0603 3882.33,1148.2 r0 top locked value=2.2uF
C44 "GCM155R71C104KA55D" 0402 1492.05,1109.51 r270 top locked value=0.1uF
C45 "CGA6P3X7R1H475M250AB" 1210_280 3903.47,1051.58 r0 top locked value=4.7uF
C46 "GCM155R71C104KA55D" 0402 4047.58,1018.12 r90 top locked value=0.1uF
C47 "GCM155R71C104KA55D" 0402 3039.25,986.63 r180 top locked value=0.1uF
C48 "GCM1555C1H681FA16D" 0402 3861.41,916.58 r0 top locked value=680pF
C49 "GCM155R71C104KA55D" 0402 4285.15,880.24 r90 top locked value=0.1uF
C50 "GCM155R71C104KA55D" 0402 3871.43,848.22 r0 top locked value=0.1uF
C51 "GCM155R71C104KA55D" 0402 636.4,746.73 r180 top locked value=0.1uF
C52 "GCM155R71C104KA55D" 0402 3411.3,595.29 r270 top locked value=0.1uF
C53 "GCM188R71E224KA55D" 0603 4301.12,582.23 r90 top locked value=0.22uF
C54 "GCM188R71E224KA55D" 0603 3667.21,578.31 r270 top locked value=0.22uF
C55 "GCM155R71C104KA55D" 0402 3518.58,577.77 r270 top locked value=0.1uF
C56 "GCM155R71H103KA55D" FP-GCM155R71H103KA55D_0402-MFG 2870.25,442.96 r180 top locked value=10nF
C57 "CGA2B2X7R1H222K050BA" 0402 636.52,182.29 r0 top locked value=2200pF
C58 "CGA2B2X7R1H222K050BA" 0402 488.13,181.81 r180 top locked value=2200pF
C59 "GCM155R71C104KA55D" 0402 2765.23,867.52 r0 bottom value=0.1uF
C500 "06035C104KAZ2A" 0603 2583.78,2498.69 r0 bottom value=0.1uF
C501 "06035C104KAZ2A" 0603 3344.38,2508.92 r270 bottom locked value=0.1uF
C502 "06035C104KAZ2A" 0603 3191.13,2508.92 r90 bottom value=0.1uF
C503 "06035C104KAZ2A" 0603 3265.63,2508.92 r90 bottom value=0.1uF
C504 "06035C104KAZ2A" 0603 2478.04,2428.23 r90 bottom locked value=0.1uF
C505 "06035C104KAZ2A" 0603 4018.17,2428.23 r90 bottom locked value=0.1uF
C506 "GCM155R71C104KA55D" 0402 1259.04,2435.24 r90 bottom locked value=0.1uF
C507 "CL05C220JB5NNNC" 0402 1208.04,2435.24 r90 bottom locked value=22pF
C508 "CL05C220JB5NNNC" 0402 1154.73,2435.24 r90 bottom locked value=22pF
C509 "CL05C220JB5NNNC" 0402 1106.42,2435.24 r90 bottom locked value=22pF
C510 "CL05C220JB5NNNC" 0402 1058.12,2435.24 r90 bottom locked value=22pF
C511 "06035C104KAZ2A" 0603 3874.2,2445.39 r180 bottom value=0.1uF
C512 "CGA4J3X7R1E225K125AB" 0805_HV 4024.1,2278.31 r0 bottom locked value=2.2uF
C513 "C1206C106J3RACAUTO" 1206_180 4039.38,2167.65 r0 bottom locked value=10uF
C514 "GCM155R71C104KA55D" 0402 4415.83,2166.65 r0 bottom locked value=0.1uF
C515 "GCM155R71C104KA55D" 0402 4303.02,2166.47 r180 bottom locked value=0.1uF
C516 "GCM188R70J225KE22D" 0603 3727.75,2112.36 r270 bottom locked value=2.2uF
C517 "CGA4J1X7R0J106K125AC" FP-CGA4J1X7R0J106K125AC_0805-MFG 699.43,2076.25 r270 bottom locked value=10µF
C518 "CGA2B2C0G1H150J050BA" 0402 2974.9,2088.43 r180 bottom locked value=15pF
C519 "GCM155R71H103KA55D" FP-GCM155R71H103KA55D_0402-MFG 3776.88,2010.04 r0 bottom locked value=10nF
C520 "GCM155R71C104KA55D" 0402 4415.83,2009.17 r0 bottom locked value=0.1uF
C521 "CGA2B2C0G1H150J050BA" 0402 2954.18,1873.66 r0 bottom locked value=15pF
C522 "GCM155R71C104KA55D" 0402 169.18,1865.47 r180 bottom locked value=0.1uF
C523 "GCM155R71C104KA55D" 0402 4415.83,1851.69 r0 bottom locked value=0.1uF
C524 "CGA1A2X7R1A103K030BA" 0201_033 2272.83,1826.6 r90 bottom locked value=0.01uF
C525 "GCM31CR70J226KE23L" 1206_180 3118.67,1762.99 r270 bottom locked value=22uF
C526 "GCM31CR70J226KE23L" 1206_180 3212.41,1762.99 r270 bottom locked value=22uF
C527 "CGA1A2X7R1A103K030BA" 0201_033 2823.35,1810.86 r90 bottom locked value=0.01uF
C528 "GCM155R71C104KA55D" 0402 765.58,1803.79 r0 bottom locked value=0.1uF
C529 "CGA1A2X7R1A103K030BA" 0201_033 2761.01,1779.36 r0 bottom locked value=0.01uF
C530 "CGA1A2X7R1A103K030BA" 0201_033 2335.82,1763.61 r90 bottom locked value=0.01uF
C531 "CGA1A2X7R1A103K030BA" 0201_033 2713.77,1763.61 r90 bottom locked value=0.01uF
C532 "CGA1A2X7R1A103K030BA" 0201_033 2398.81,1763.61 r90 bottom locked value=0.01uF
C533 "CGA1A2X7R1A103K030BA" 0201_033 2620.78,1763.37 r90 bottom locked value=0.01uF
C534 "CGA1A2X7R1A103K030BA" 0201_033 2586.29,1763.37 r270 bottom locked value=0.01uF
C535 "GCM31CR70J226KE23L" 1206_180 3710.96,1699.91 r90 bottom locked value=22uF
C536 "GCM31CR70J226KE23L" 1206_180 3857.58,1729.88 r180 bottom locked value=22uF
C537 "GCM31CR70J226KE23L" 1206_180 4068.77,1729.87 r0 bottom locked value=22uF
C538 "CGA1A2X7R1A103K030BA" 0201_033 2789.75,1747.86 r0 bottom locked value=0.01uF
C539 "CGA1A2X7R1A103K030BA" 0201_033 2464.56,1732.12 r90 bottom locked value=0.01uF
C540 "CGA1A2X7R1A103K030BA" 0201_033 2430.31,1732.12 r90 bottom locked value=0.01uF
C541 "CGA1A2X7R1A103K030BA" 0201_033 2510.64,1716.7 r180 bottom locked value=0.01uF
C542 "CGA1A2X7R1A103K030BA" 0201_033 2604.19,1716.37 r180 bottom locked value=0.01uF
C543 "CGA1A2X7R1A103K030BA" 0201_033 2556.29,1700.62 r90 bottom locked value=0.01uF
C544 "CGA1A2X7R1A103K030BA" 0201_033 2650.78,1700.62 r90 bottom locked value=0.01uF
C545 "CGA1A2X7R1A103K030BA" 0201_033 2430.31,1669.12 r90 bottom locked value=0.01uF
C546 "CGA1A2X7R1A103K030BA" 0201_033 2493.3,1669.12 r270 bottom locked value=0.01uF
C547 "CGA1A2X7R1A103K030BA" 0201_033 2726.76,1682.12 r0 bottom locked value=0.01uF
C548 "CGA1A2X7R1A103K030BA" 0201_033 2666.53,1653.38 r180 bottom locked value=0.01uF
C549 "CGA1A2X7R1A103K030BA" 0201_033 2540.54,1653.38 r180 bottom locked value=0.01uF
C550 "CGA1A2X7R1A103K030BA" 0201_033 2604.12,1653.38 r180 bottom locked value=0.01uF
C551 "CGA1A2X7R1A103K030BA" 0201_033 2540.54,1621.88 r180 bottom locked value=0.01uF
C552 "CGA1A2X7R1A103K030BA" 0201_033 2726.76,1621.88 r0 bottom locked value=0.01uF
C553 "CGA1A2X7R1A103K030BA" 0201_033 2448.81,1621.88 r0 bottom locked value=0.01uF
C554 "CGA1A2X7R1A103K030BA" 0201_033 2679.52,1606.13 r270 bottom locked value=0.01uF
C555 "CGA1A2X7R1A103K030BA" 0201_033 2398.81,1606.13 r270 bottom locked value=0.01uF
C556 "CGA1A2X7R1A103K030BA" 0201_033 2635.03,1590.38 r180 bottom locked value=0.01uF
C557 "CGA1A2X7R1A103K030BA" 0201_033 2448.81,1588.38 r0 bottom locked value=0.01uF
C558 "CGA1A2X7R1A103K030BA" 0201_033 2713.77,1574.64 r270 bottom locked value=0.01uF
C559 "GCM31CR70J226KE23L" 1206_180 3145.36,1507.47 r270 bottom locked value=22uF
C560 "CGA1A2X7R1A103K030BA" 0201_033 2635.03,1558.89 r180 bottom locked value=0.01uF
C561 "CGA3E2C0G1H330J080AA" FP-CGA3E2C0G1H330J080AA_0603-MFG 3226.95,1514.81 r90 bottom locked value=33pF
C562 "CGA1A2X7R1A103K030BA" 0201_033 2430.31,1514.4 r270 bottom locked value=0.01uF
C563 "CGA1A2X7R1A103K030BA" 0201_033 2700.78,1527.39 r180 bottom locked value=0.01uF
C564 "CGA1A2X7R1A103K030BA" 0201_033 2477.55,1527.39 r0 bottom locked value=0.01uF
C565 "CGA4J3X7R1E225K125AB" 0805_HV 3645.48,1453.87 r90 bottom locked value=2.2uF
C566 "CGA1A2X7R1A103K030BA" 0201_033 2619.28,1480.15 r90 bottom locked value=0.01uF
C567 "CGA1A2X7R1A103K030BA" 0201_033 2713.77,1480.15 r90 bottom locked value=0.01uF
C568 "CGA1A2X7R1A103K030BA" 0201_033 2682.27,1480.15 r90 bottom locked value=0.01uF
C569 "CGA1A2X7R1A103K030BA" 0201_033 2524.79,1448.65 r90 bottom locked value=0.01uF
C570 "CGA1A2X7R1A103K030BA" 0201_033 2493.3,1448.65 r90 bottom locked value=0.01uF
C571 "CGA3E2X7R1H104K080AA" 0603 4445.83,1413.5 r90 bottom locked value=0.1uF
C572 "GCM188R70J225KE22D" 0603 1058.92,1445.8 r180 bottom locked value=2.2uF
C573 "GCM188R70J225KE22D" 0603 1224.78,1444.08 r180 bottom locked value=2.2uF
C574 "CGA1A2X7R1A103K030BA" 0201_033 2411.8,1435 r0 bottom locked value=0.01uF
C575 "CGA1A2X7R1A103K030BA" 0201_033 2716.53,1417.16 r90 bottom locked value=0.01uF
C576 "CGA1A2X7R1A103K030BA" 0201_033 2679.52,1417.16 r90 bottom locked value=0.01uF
C577 "CGA1A2X7R1A103K030BA" 0201_033 2648.02,1417.16 r90 bottom locked value=0.01uF
C578 "CGA1A2X7R1A103K030BA" 0201_033 2461.57,1416.77 r270 bottom locked value=0.01uF
C579 "CGA1A2X7R1A103K030BA" 0201_033 2493.3,1388.42 r270 bottom locked value=0.01uF
C580 "CGA1A2X7R1A103K030BA" 0201_033 2601.53,1398.65 r180 bottom locked value=0.01uF
C581 "CGA1A2X7R1A103K030BA" 0201_033 2385.82,1401.41 r180 bottom locked value=0.01uF
C582 "CGA1A2X7R1A103K030BA" 0201_033 2539.79,1398.65 r180 bottom locked value=0.01uF
C583 "CGA1A2X7R1A103K030BA" 0201_033 2617.18,1325.61 r270 bottom locked value=0.01uF
C584 "CGA1A2X7R1A103K030BA" 0201_033 2713.77,1325.42 r270 bottom locked value=0.01uF
C585 "CGA1A2X7R1A103K030BA" 0201_033 2508.29,1338.42 r0 bottom locked value=0.01uF
C586 "CGA1A2X7R1A103K030BA" 0201_033 2335.82,1323.26 r270 bottom locked value=0.01uF
C587 "GCM188R71C105KA64D" 0603 4309.22,1295.01 r0 bottom locked value=1uF
C588 "CGA1A2X7R1A103K030BA" 0201_033 2748.02,1279.52 r180 bottom locked value=0.01uF
C589 "GCM188R70J225KE22D" 0603 3873.12,1244.4 r0 bottom locked value=2.2uF
C590 "CGA4J3X7R1E225K125AB" 0805_HV 3892.87,1163.7 r0 bottom locked value=2.2uF
C591 "C1206C106J3RACAUTO" 1206_180 4047.58,1061.43 r90 bottom locked value=10uF
C592 "CGA4J3X7R1E225K125AB" 0805_HV 3892.87,1063.7 r0 bottom locked value=2.2uF
C593 "GCM155R71C104KA55D" 0402 932.17,1049.34 r90 bottom locked value=0.1uF
C594 "GCM155R71C104KA55D" 0402 4439.13,1039.6 r90 bottom locked value=0.1uF
C595 "GCM155R71C104KA55D" 0402 2844.57,1063.11 r0 bottom locked value=0.1uF
C596 "GCM155R71C104KA55D" 0402 1316.13,994.97 r90 bottom locked value=0.1uF
C597 "GCM155R71C104KA55D" 0402 1130.85,967.41 r270 bottom locked value=0.1uF
C598 "GCM155R71C104KA55D" 0402 1966.45,952.9 r90 bottom locked value=0.1uF
C599 "GCM155R71C104KA55D" 0402 2708.24,954.84 r180 bottom locked value=0.1uF
C600 "CGA4J3X7R1E225K125AB" 0805_HV 4285.15,896.61 r90 bottom locked value=2.2uF
C601 "GCM188R70J225KE22D" 0603 4063.07,864.33 r270 bottom locked value=2.2uF
C602 "GCM155R71C104KA55D" 0402 4003.07,872.21 r270 bottom locked value=0.1uF
C603 "GCM155R71C104KA55D" 0402 1316.13,859.4 r270 bottom locked value=0.1uF
C604 "CGA4J3X7R1E225K125AB" 0805_HV 3887.81,848.22 r0 bottom locked value=2.2uF
C605 "GCM188R71C105KA64D" 0603 1221.52,829.5 r180 bottom locked value=1uF
C606 "GCM155R71C104KA55D" 0402 636.4,828.47 r180 bottom locked value=0.1uF
C607 "CGA2B2X7R1H331K050BA" 0402 3730.2,809.78 r180 bottom locked value=330pF
C608 "GCM155R71C104KA55D" 0402 2866.34,737.89 r180 bottom locked value=0.1uF
C609 "GCM155R71C104KA55D" 0402 3132.92,703.17 r180 bottom locked value=0.1uF
C610 "CGA5L2X7R1H474K160AA" 1206_180 3765.66,605.33 r270 bottom locked value=0.47uF
C611 "GCM155R71H103KA55D" FP-GCM155R71H103KA55D_0402-MFG 4205.39,663.93 r270 bottom locked value=10nF
C612 "CGA4J1X7R0J106K125AC" FP-CGA4J1X7R0J106K125AC_0805-MFG 3120.12,644.59 r0 bottom locked value=10µF
C613 "08055C105K4Z2A" 0805_HV 4301.12,590.74 r90 bottom locked value=1uF
C614 "GCM155R71C104KA55D" 0402 1258.79,635.93 r0 bottom locked value=0.1uF
C615 "CGA4J3X7R1E225K125AB" 0805_HV 3518.58,561.39 r270 bottom locked value=2.2uF
C616 "08055C105K4Z2A" 0805_HV 3624.03,561.33 r270 bottom locked value=1uF
C617 "GCM155R71C104KA55D" 0402 4425.13,580.9 r90 bottom locked value=0.1uF
C618 "CL05C220JB5NNNC" 0402 1534.15,298.56 r180 bottom locked value=22pF
C619 "CL05C220JB5NNNC" 0402 3846.59,214.03 r90 bottom locked value=22pF
C620 "CL05C220JB5NNNC" 0402 927.67,202.58 r0 bottom locked value=22pF
C621 "CL05C220JB5NNNC" 0402 797.48,202.58 r180 bottom locked value=22pF
C622 "CGA2B2X7R1H222K050BA" 0402 439.13,182.03 r180 bottom locked value=2200pF
C623 "CL05C220JB5NNNC" 0402 1734.71,104.15 r270 bottom locked value=22pF
C624 "CL05C220JB5NNNC" 0402 3846.49,103.82 r270 bottom locked value=22pF
C625 "CL05C220JB5NNNC" 0402 1580.72,55.12 r0 bottom locked value=22pF
C626 "CL05C220JB5NNNC" 0402 1433.86,55.12 r180 bottom locked value=22pF
C627 "CL05C220JB5NNNC" 0402 3687.15,51.75 r0 bottom locked value=22pF
C628 "CL05C220JB5NNNC" 0402 3539.59,51.75 r180 bottom locked value=22pF
D1 "PMEG10030ELPX" SOD-128 4059.06,2167.65 r0 top locked value=100V
D2 "LTST-C171GKT" LED_LTST-C171 660.45,1553.12 r180 top locked value=Green
D3 "LTST-C171GKT" LED_LTST-C171 642.8,1452.12 r0 top locked value=Green
D4 "LTST-C171KRKT" FP-LTST-C171KRKT_0805-MFG 666.39,1351.12 r0 top locked
D5 "SZMM5Z6V2T1G" FP-SZMM5Z6V2T1G_SOD523-MFG 3863.77,965.59 r0 top locked
D6 "MBR0540T1G" SOD-123 4205.39,615.2 r270 top locked value=40V
"ESD Susceptible1" "ESD Susceptible" ESD_Overlay_Small 4209.23,1942.74 r0 top
FB1 "MMZ1005Y121CTD25" FP-MMZ1005Y121CTD25_0402-MFG 1315.73,2332.66 r90 top locked
FB2 "MMZ1005Y121CTD25" FP-MMZ1005Y121CTD25_0402-MFG 1355.43,2332.66 r90 top locked
FB3 "MMZ1005Y121CTD25" FP-MMZ1005Y121CTD25_0402-MFG 1395.13,2332.66 r90 top locked
FB500 "MMZ1005Y121CTD25" FP-MMZ1005Y121CTD25_0402-MFG 1237.32,2315.36 r90 bottom locked
FID1 "Fiducial" Fiducial10-20 390.87,2511.7 r180 bottom locked
FID2 "Fiducial" Fiducial10-20 390.87,2511.7 r0 top locked
FID3 "Fiducial" Fiducial10-20 119.47,435.75 r180 bottom locked
FID4 "Fiducial" Fiducial10-20 119.47,435.75 r0 top locked
FID5 "Fiducial" Fiducial10-20 4436.59,322.63 r180 bottom locked
FID6 "Fiducial" Fiducial10-20 4436.59,322.63 r0 top locked
J1 "5051108091" FP-5051108091_CONN_FFC_FPC_80-MFG 3251.1,2491.14 r180 top locked
J2 "501331-0907" FP-501331-0907_HDR9-MFG 1237.32,2506.5 r180 top locked
J3 "5023520600" FP-5023520600_HDR6-MFG 4614.17,1939.8 r90 top locked
J4 "HD04-19-TH-TR" FP-HD04-19-TH-TR_CONN_HDMI_RCPT19-MFG 232.28,1860.68 r270 top locked
J5 "5023520200" FP-5023520200_HDR2-MFG 4614.17,1413.5 r90 top locked
J6 "505110-1692" FP-505110-1692_CONN_SMT_12MM7_5MM25-MFG 107.28,1003.36 r270 top locked
J7 "502352-0300" Molex_502352-0300 4618.11,1000.23 r90 top locked
J8 "502352-0300" Molex_502352-0300 4618.11,541.53 r90 top locked
J9 "1734346-1" CONN_USB-1734346 2268.71,500 r270 top locked
J10 "61300311121" WURTH_61300311121 501.42,539.87 r90 top locked
J11 "61300311121" WURTH_61300311121 711.44,539.87 r90 top locked
J12 "61300311121" WURTH_61300311121 291.4,539.87 r90 top locked
J13 "61300311121" WURTH_61300311121 921.46,539.87 r90 top locked
J14 "502352-0200" FP-502352-0200_HDR2-MFG 2878.12,188.98 r0 top locked
J15 "702461002" FP-702461002_HDR10-MFG 1457.29,178.94 r0 top locked
J16 "702461002" FP-702461002_HDR10-MFG 3563.48,178.94 r0 top locked
J17 "61300611121" WURTH_61300611121 662.58,95.27 r180 top locked
J500 "5051102091" FP-5051102091_CONN_FFC_FPC20-MFG 1951.1,2429.53 r0 bottom locked
L1 "7427920415" 0805_HV 741.96,1768.67 r270 top locked value="600 ohm"
L2 "XAL5050-223MEB" XAL5050 3969.98,1534.72 r90 top locked value=22uH
L3 "7427920415" 0805_HV 1049.59,1445.8 r0 top locked value="600 ohm"
L4 "7427920415" 0805_HV 1374.94,1445.41 r180 top locked value="600 ohm"
L5 "MPZ2012S101ATD25" FP-MPZ2012S101ATD25_0805-MFG 4338.63,1416.98 r90 top locked
L6 "120OHM @ 100MHZ" FP-MMZ1005Y121CTD25_0402-MFG 4348.34,1000.23 r0 top locked
L7 "120OHM @ 100MHZ" FP-MMZ1005Y121CTD25_0402-MFG 4063.07,878.11 r90 top locked
L8 "CDRH5D18NP-100NC" CDRH5D18 4004.88,610.64 r270 top locked value=10uH
L500 "120OHM @ 100MHZ" FP-MMZ1005Y121CTD25_0402-MFG 2145.03,2308.17 r90 bottom locked
L501 "120OHM @ 100MHZ" FP-MMZ1005Y121CTD25_0402-MFG 2110.23,2308.17 r90 bottom locked
L502 "120OHM @ 100MHZ" FP-MMZ1005Y121CTD25_0402-MFG 2075.43,2308.17 r90 bottom locked
L503 "120OHM @ 100MHZ" FP-MMZ1005Y121CTD25_0402-MFG 2040.63,2308.17 r90 bottom locked
L504 "120OHM @ 100MHZ" FP-MMZ1005Y121CTD25_0402-MFG 2005.84,2308.17 r90 bottom locked
L505 "120OHM @ 100MHZ" FP-MMZ1005Y121CTD25_0402-MFG 1971.04,2308.17 r90 bottom locked
L506 "120OHM @ 100MHZ" FP-MMZ1005Y121CTD25_0402-MFG 1936.24,2308.17 r90 bottom locked
L507 "120OHM @ 100MHZ" FP-MMZ1005Y121CTD25_0402-MFG 1901.45,2308.17 r90 bottom locked
L508 "120OHM @ 100MHZ" FP-MMZ1005Y121CTD25_0402-MFG 1866.65,2308.17 r90 bottom locked
L509 "120OHM @ 100MHZ" FP-MMZ1005Y121CTD25_0402-MFG 1831.85,2308.17 r90 bottom locked
L510 "120OHM @ 100MHZ" FP-MMZ1005Y121CTD25_0402-MFG 1797.05,2308.17 r90 bottom locked
L511 "120OHM @ 100MHZ" FP-MMZ1005Y121CTD25_0402-MFG 1762.26,2308.17 r90 bottom locked
L512 "74279228111" 0603 2206.47,2263.79 r270 bottom locked value="110 ohm"
L513 "74279228111" 0603 2269.46,2263.79 r270 bottom locked value="110 ohm"
L514 "7427920415" 0805_HV 788.2,2076.25 r270 bottom locked value="600 ohm"
L515 "74279228111" 0603 2094.57,2125.08 r0 bottom locked value="110 ohm"
L516 "CDRH5D18NP-100NC" CDRH5D18 4113.22,1947.41 r90 bottom locked value=10uH
L517 "74279228111" 0603 2094.57,2062.09 r0 bottom locked value="110 ohm"
L518 "XFL4020-222MEB" XFL4020 3357.16,1829.85 r180 bottom locked value=2.2uH
L519 "74279228111" 0603 2966.47,1688.62 r180 bottom locked value="110 ohm"
L520 "XFL4020-222MEB" XFL4020 3357.16,1589.05 r180 bottom locked value=2.2uH
L521 "74279228111" 0603 2966.47,1626.13 r180 bottom locked value="110 ohm"
L522 "74279228111" 0603 2981.73,1491.04 r180 bottom locked value="110 ohm"
L523 "74279228111" 0603 2978.77,1329.92 r180 bottom locked value="110 ohm"
L524 "74279228111" 0603 2820.94,1169.59 r270 bottom locked value="110 ohm"
L525 "120OHM @ 100MHZ" FP-MMZ1005Y121CTD25_0402-MFG 4366.17,903.78 r90 bottom locked
L526 "120OHM @ 100MHZ" FP-MMZ1005Y121CTD25_0402-MFG 4366.11,445.08 r90 bottom locked
Logo1 "Texas Instruments" TI_Stacked_Overlay_Small 4696.9,1353.98 r90 bottom
Logo2 "FCC disclaimer" FCC_disclaimer 23.61,810.93 r90 bottom
Logo3 "CE Mark" CE_Mark_5mm 572.49,1282.88 r180 bottom
Logo4 "WEEE logo" WEEE_Minimum 4657.96,527.97 r180 bottom
MH1 "MTG_Pads" MTGP_252mil_157mil_6Via 181.1,2417.32 r0 top locked
MH2 "MTG_Pads" MTGP_252mil_157mil_6Via 4622.05,2417.32 r0 top locked
MH3 "MTG_Pads" MTGP_252mil_157mil_6Via 181.1,181.1 r0 top locked
MH4 "MTG_Pads" MTGP_252mil_157mil_6Via 4622.05,181.1 r0 top locked
Q1 "NX3008NBKW,115" SOT-323 4171.7,947.77 r90 top locked value=30V
R1 "ERJ-2GEJ103X" 0402 947.73,2161.08 r90 top locked value=10k
R2 "ERJ-2GEJ103X" 0402 593.75,2098.24 r90 top locked value=10k
R3 "ERJ-2GEJ103X" 0402 971.35,2079.54 r180 top locked value=10k
R4 "ERJ-2RKF1002X" 0402 3881.47,2010.55 r270 top locked value=10.0k
R5 "ERJ-2GEJ103X" 0402 3661.45,1985.18 r0 top locked value=10k
R6 "ERJ-2GEJ103X" 0402 2002.79,1937.94 r270 top value=10k
R7 "ERJ-2GEJ103X" 0402 2077.78,1937.94 r270 top locked value=10k
R8 "ERJ-2GEJ103X" 0402 2152.78,1937.94 r270 top locked value=10k
R9 "300" FP-ERJ-2RKF3000X_0402-MFG 3511.22,1861.88 r270 top locked
R10 "ERJ-2RKF33R0X" 0402 2002.79,1821.94 r90 top locked value=33.0
R11 "ERJ-2RKF33R0X" 0402 2077.78,1821.94 r90 top locked value=33.0
R12 "ERJ-2RKF33R0X" 0402 2152.78,1821.94 r90 top locked value=33.0
R13 "ERJ-2GEJ103X" 0402 3372.21,1729.87 r0 top locked value=10k
R14 "ERJ-2GEJ103X" 0402 3634.38,1668.1 r90 top locked value=10k
R15 "ERJ-2RKF33R0X" 0402 1644.23,1692.37 r0 top locked value=33.0
R16 "ERJ-2GEJ103X" 0402 3372.21,1679.87 r0 top locked value=10k
R17 "ERJ-2RKF33R0X" 0402 1644.23,1641.37 r0 top locked value=33.0
R18 "ERJ-2GEJ103X" 0402 2011.4,1629.72 r0 top locked value=10k
R19 "ERJ-2RKF33R0X" 0402 2133.94,1629.72 r180 top locked value=33.0
R20 "ERJ-2GEJ103X" 0402 4154.95,1622.27 r180 top locked value=10k
R21 "ERJ-2GEJ103X" 0402 3600.5,1584.74 r0 top locked value=10k
R22 "ERJ-2GEJ103X" 0402 2011.4,1560.12 r0 top locked value=10k
R23 "ERJ-2GEJ103X" 0402 2133.94,1560.12 r0 top locked value=10k
R24 "ERJ-2RKF1503X" 0402 3226.95,1512.75 r90 top locked value=150k
R25 "CRCW0402150RFKED" 0402 493.55,1513.12 r180 top locked value=150
R26 "ERJ-2GEJ103X" 0402 2133.44,1485.52 r0 top value=10k
R27 "CRCW04021K00FKED" 0402 3686.78,1427.87 r270 top locked value=1.00k
R28 "ERJ-2GEJ103X" 0402 3401.3,1425.4 r270 top locked value=10k
R29 "ERJ-2GEJ103X" 0402 3452.3,1425.4 r270 top locked value=10k
R30 "ERJ-2GEJ103X" 0402 3503.3,1425.4 r270 top locked value=10k
R31 "CRCW0402150RFKED" 0402 493.55,1452.12 r180 top locked value=150
R32 "RC0402FR-07180KL" 0402 3250.66,1430.14 r180 top locked value=180k
R33 "ERJ-2GEJ103X" 0402 2132.8,1420.91 r0 top locked value=10k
